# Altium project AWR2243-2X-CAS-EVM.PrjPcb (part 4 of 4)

## Sheet Enet_Conn.SchDoc
size 431 x 279 mm; Date: Not shown in title block; ApprovedBy: Not shown in title block; CheckedBy: Not shown in title block; Author: Not shown in title block; CompanyName: Not shown in title block; DrawnBy: B. Shaffer; Engineer: Not shown in title block; Organization: Not shown in title block; Address1: Not shown in title block; Address2: Not shown in title block; Address3: Not shown in title block; Address4: Not shown in title block; DocumentNumber: 12; Revision: Use project parameter SCH_Rev; SheetNumber: 12; SheetTotal: 17; PageSetup: Record=PageOptions¦CenterHorizontal=True¦CenterVertical=True¦PrintScale=1.00¦XCorrection=1.00¦YCorrection=1.00¦PrintKind=0¦BorderSize=5000000¦LeftOffset=0¦BottomOffset=0¦Orientation=2¦PaperLength=1000¦PaperWidth=1000¦Scale=100¦PaperSource=15¦PrintQuality=600¦MediaType=1¦DitherType=10¦PaperKind=Letter¦PrintScaleMode=1
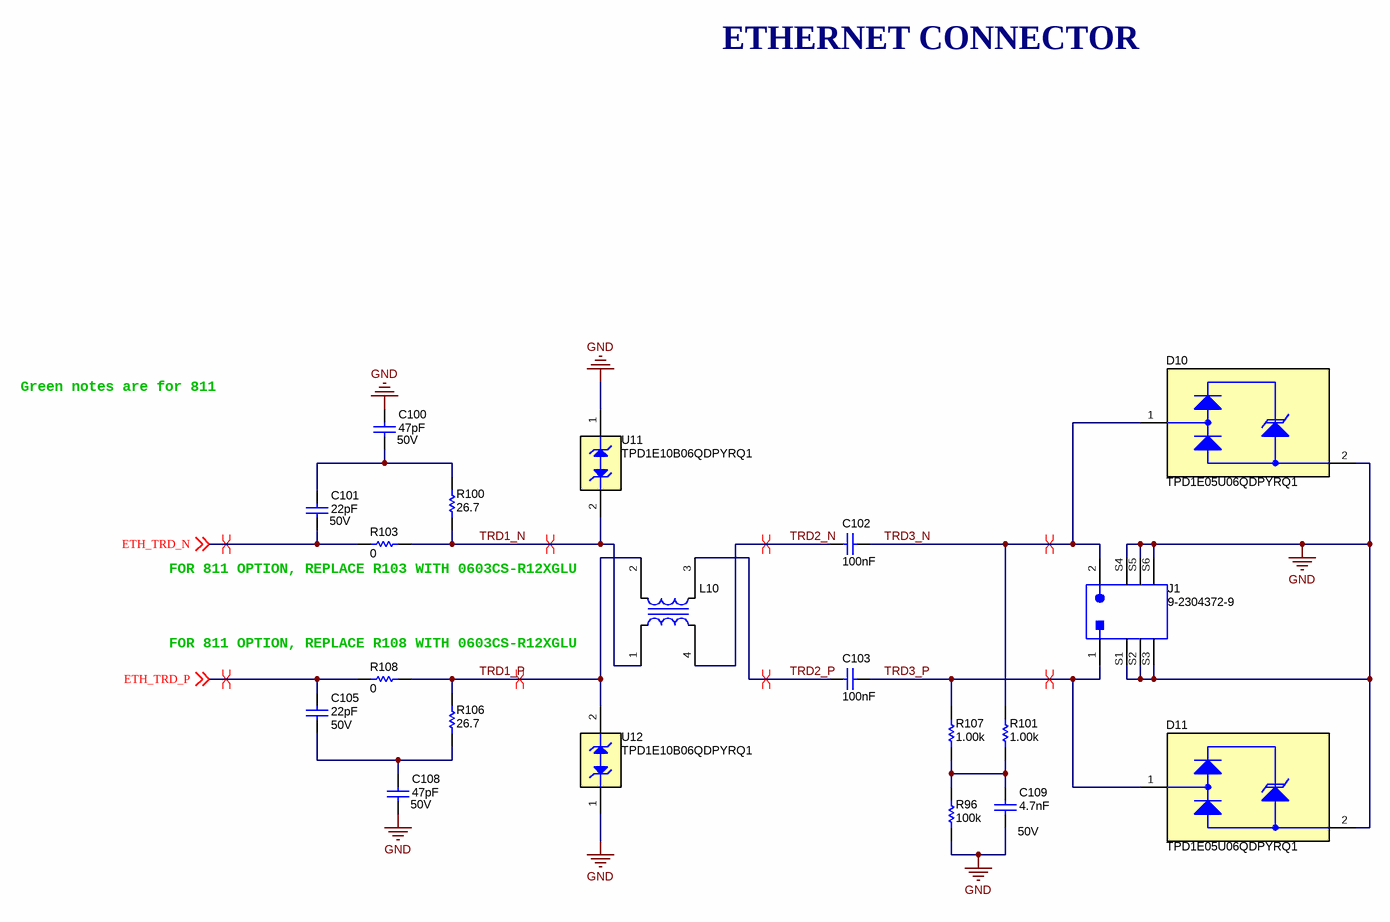
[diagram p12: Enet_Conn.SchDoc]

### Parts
C100  VDC_V: 50V  ValueDisplayed: 47pF  [0402]  (hidden comment: GRM1555C1H470FA01D)
C101  VDC_V: 50V  ValueDisplayed: 22pF  [0402]  (hidden comment: GRM1555C1H220FA01D)
C102  Cap_F: 100nF  [0805_HV]  (hidden comment: CGA4J2X7R2A104K125AA)
C103  Cap_F: 100nF  [0805_HV]  (hidden comment: CGA4J2X7R2A104K125AA)
C105  VDC_V: 50V  ValueDisplayed: 22pF  [0402]  (hidden comment: GRM1555C1H220FA01D)
C108  VDC_V: 50V  ValueDisplayed: 47pF  [0402]  (hidden comment: GRM1555C1H470FA01D)
C109  Cap_F: 4.7nF  VDC_V: 50V  [0805_HV]  (hidden comment: GCM216R71H472KA37D)
D10  TPD1E05U06QDPYRQ1  [DPY0002A]
D11  TPD1E05U06QDPYRQ1  [DPY0002A]
J1  9-2304372-9  [TE_9-2304372-9]
L10  ACT1210-101-2P-TL00  [TDK_ACT1210]  (value not drawn)
R96  ValueDisplayed: 100k  [0805_HV]  (hidden comment: CRCW0805100KJNEA)
R100  ValueDisplayed: 26.7  [0402]  (hidden comment: CRCW040226R7FKED)
R101  ValueDisplayed: 1.00k  [0402]  (hidden comment: CRCW04021K00FKED)
R103  ValueDisplayed: 0  [0603]  (hidden comment: RMCF0603ZT0R00)
R106  ValueDisplayed: 26.7  [0402]  (hidden comment: CRCW040226R7FKED)
R107  ValueDisplayed: 1.00k  [0402]  (hidden comment: CRCW04021K00FKED)
R108  ValueDisplayed: 0  [0603]  (hidden comment: RMCF0603ZT0R00)
U11  TPD1E10B06QDPYRQ1  [DPY0002A]
U12  TPD1E10B06QDPYRQ1  [DPY0002A]

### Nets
GND: C100.1 C108.2 C109.2 D10.2(GND) D11.2(GND) J1.S1(GND) J1.S2(GND) J1.S3(GND) J1.S4(GND) J1.S5(GND) J1.S6(GND) R96.1 U11.1(K) U12.1(K)
ETH_TRD_N: C101.2 R103.1 ; off-sheet ETH_TRD_N
ETH_TRD_P: C105.1 R108.1 ; off-sheet ETH_TRD_P
TRD1_N: L10.1 R100.1 R103.2 U11.2(A)
TRD1_P: L10.2 R106.2 R108.2 U12.2(A)
TRD2_N: C102.2 L10.4
TRD2_P: C103.2 L10.3
TRD3_N: C102.1 D10.1(I/O) J1.2 R101.2
TRD3_P: C103.1 D11.1(I/O) J1.1 R107.2
NetC100_2: C100.2 C101.1 R100.2
NetC105_2: C105.2 C108.1 R106.1
NetC109_1: C109.1 R96.2 R101.1 R107.1

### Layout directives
differential pair: ETH_TRD_N, ETH_TRD_P, TRD1_N, TRD1_P, TRD2_N, TRD2_P, TRD3_N, TRD3_P

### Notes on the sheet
- ETHERNET CONNECTOR
- Green notes are for 811
- (near R103) FOR 811 OPTION, REPLACE R103 WITH 0603CS-R12XGLU
- (near R108) FOR 811 OPTION, REPLACE R108 WITH 0603CS-R12XGLU

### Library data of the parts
C100 C108 = CMP-0006467-2: CAP, CERM, 47 pF, 50 V, +/- 1%, C0G/NP0, 0402; Manufacturer: MuRata; TaMin_C: -55°C; Polarized: N; SizeAreaWB_mm2: 3; Value1: Unknown; U/M: EA; Value: 47pF; TaMax_C: 125°C; SizeZ_mm: 0.6; SizeX_mm: 1; SizeY_mm: 0.5; CompType: Capacitor; AEC Category: Q200
C101 C105 = CMP-0006438-2: CAP, CERM, 22 pF, 50 V, +/- 1%, C0G/NP0, 0402; Manufacturer: MuRata; TaMin_C: -55°C; Polarized: N; SizeAreaWB_mm2: 3; Value1: Unknown; U/M: EA; Value: 22pF; TaMax_C: 125°C; SizeZ_mm: 0.6; SizeX_mm: 1; SizeY_mm: 0.5; CompType: Capacitor; AEC Category: Q200
C102 C103 = CMP-0007969-2: CAP, CERM, 0.1 uF, 100 V, +/- 10%, X7R, AEC-Q200 Grade 1, 0805; Manufacturer: TDK; TaMin_C: -55°C; ESR_ohm: 0.020726; Polarized: N; SizeAreaWB_mm2: 6.75; Value1: 0.020726 ohm; U/M: EA; Value: 0.1uF; TaMax_C: 125°C; SizeZ_mm: 1.45; SizeX_mm: 2; SizeY_mm: 1.25; Cap_Case: 0805; Value2: 100V; SizeArea_mm2: 2.5; AEC Qualified: Y; IRMS_A: 1.456A; AEC Grade: 1; AEC Category: Q200
C109 = CMP-0079078-1: CAP, CERM, 4700 pF, 50 V,+/- 10%, X7R, AEC-Q200 Grade 1, 0805; Manufacturer: MuRata; SizeAreaWB_mm2: 6.75; SizeArea_mm2: 2.5; AEC Qualified: Y; AEC Category: Q200; Value: 4700pF; TaMax_C: 125°C; SizeZ_mm: 1.45; AEC Grade: 1; Polarized: N; TaMin_C: -55°C; SizeY_mm: 1.25; U/M: EA; CompType: Capacitor; SizeX_mm: 2; Cap_Case: 0805
D10 D11 = CMP-0073591-4: Automotive 1-Channel Ultra-Low-Capacitance IEC ESD Protection Diode, DPY0002A (X1SON-2); Alternate Manufacturer: Texas Instruments; Alternate PartNumber: TPD1E05U06QDPYTQ1; SizeZ_mm: 0.45; SizeAreaWB_mm2: 3.2; SizeArea_mm2: 0.6; CompType: IC; AEC Category: Q200; AEC Qualified: Y; SizeX_mm: 1.0
J1 = CMP-0078655-1: 1 Port Header Assembly, TH; Manufacturer: TE Connectivity; Gender: Male; CompType: Connector; Shrouded: Y
L10 = CMP-0013193-2: Coupled inductor, 100 uH,  A, 1.5 ohm, SMD; Manufacturer: TDK; SizeAreaWB_mm2: 17.15; DCR_ohm: 1.5; Value: 100uH; SizeZ_mm: 2.5; SizeX_mm: 3.9; SizeArea_mm2: 9.75; Ind_H: 100µH
R96 = CMP-0020444-3: RES, 100 k, 5%, 0.125 W, AEC-Q200 Grade 0, 0805; Manufacturer: Vishay-Dale; Power_W: 125mW; TempCo: 200 ppm/C; Value: 100k; EIA_Code: E24; SizeX_mm: 2; SizeY_mm: 1.25; SizeZ_mm: 1.45; Value2: 0.125W; SizeArea_mm2: 2.5; AEC Qualified: Y; VDC_V: 150V; AEC Category: Q200; AEC Grade: 0
R100 = CMP-0026210-2: RES, 26.7, 1%, 0.063 W, AEC-Q200 Grade 0, 0402; Manufacturer: Vishay-Dale; Power_W: 63mW; TempCo: 100 ppm/C; Value_Code: 26R7; Value: 26.7; SizeX_mm: 1; SizeY_mm: 0.5; SizeZ_mm: 0.6; Value2: 0.063W; AEC Qualified: Y; VDC_V: 50V; AEC Grade: 0; AEC Category: Q200; EIA_Code: E96
R101 R107 = CMP-0026071-3: RES, 1.00 k, 1%, 0.063 W, AEC-Q200 Grade 0, 0402; Manufacturer: Vishay-Dale; Power_W: 63mW; TempCo: 100 ppm/C; Value_Code: 1k00; Value: 1.00k; EIA_Code: E96; Res_ohm: 1k; SizeX_mm: 1; SizeY_mm: 0.5; SizeZ_mm: 0.6; Value2: 0.063W; AEC Qualified: Y; VDC_V: 50V; AEC Category: Q200; AEC Grade: 0
R103 R108 = CMP-0023343-3: RES, 0, 1%, 0.1 W, AEC-Q200 Grade 0, 0603; Manufacturer: Stackpole Electronics Inc; Power_W: 100mW; TempCo: ppm/C; U/M: EA; Value: 0; SizeX_mm: 1.6; SizeY_mm: 0.8; SizeZ_mm: 1; Value2: 0.1W; SizeArea_mm2: 1.28; AEC Qualified: Y; AEC Category: Q200
R106 = CMP-0026210-2: RES, 26.7, 1%, 0.063 W, AEC-Q200 Grade 0, 0402; Manufacturer: Vishay-Dale; Power_W: 63mW; TempCo: 100 ppm/C; Value_Code: 26R7; Value: 26.7; SizeX_mm: 1; SizeY_mm: 0.5; SizeZ_mm: 0.6; Value2: 0.063W; CompType: Resistor; AEC Qualified: Y; VDC_V: 50V; AEC Grade: 0; AEC Category: Q200; EIA_Code: E96
U11 U12 = CMP-0073592-4: Automotive 1-Channel ESD in 0402 Package With 12pF Capacitance and 6V Breakdown, DPY0002A (X1SON-2); Manufacturer: Texas Instruments; Alternate PartNumber: TPD1E10B06DPYR; AEC Qualified: Y; AEC Category: Q200; CompType: IC; SizeAreaWB_mm2: 3.2; SizeZ_mm: 0.45; SizeY_mm: 0.6; SizeX_mm: 1.0

## Sheet Temp.schdoc: XDS110 Interface_1A
size 431 x 279 mm; Date: Not shown in title block; ApprovedBy: Not shown in title block; CheckedBy: Not shown in title block; Author: Not shown in title block; CompanyName: Not shown in title block; DrawnBy: B. Shaffer; Engineer: Not shown in title block; Organization: Not shown in title block; Address1: Not shown in title block; Address2: Not shown in title block; Address3: Not shown in title block; Address4: Not shown in title block; DocumentNumber: 13; Revision: Use project parameter SCH_Rev; SheetNumber: 13; SheetTotal: 17; PageSetup: Record=PageOptions¦CenterHorizontal=True¦CenterVertical=True¦PrintScale=1.00¦XCorrection=1.00¦YCorrection=1.00¦PrintKind=0¦BorderSize=5000000¦LeftOffset=0¦BottomOffset=0¦Orientation=2¦PaperLength=1000¦PaperWidth=1000¦Scale=100¦PaperSource=15¦PrintQuality=600¦MediaType=1¦DitherType=10¦PaperKind=Letter¦PrintScaleMode=1
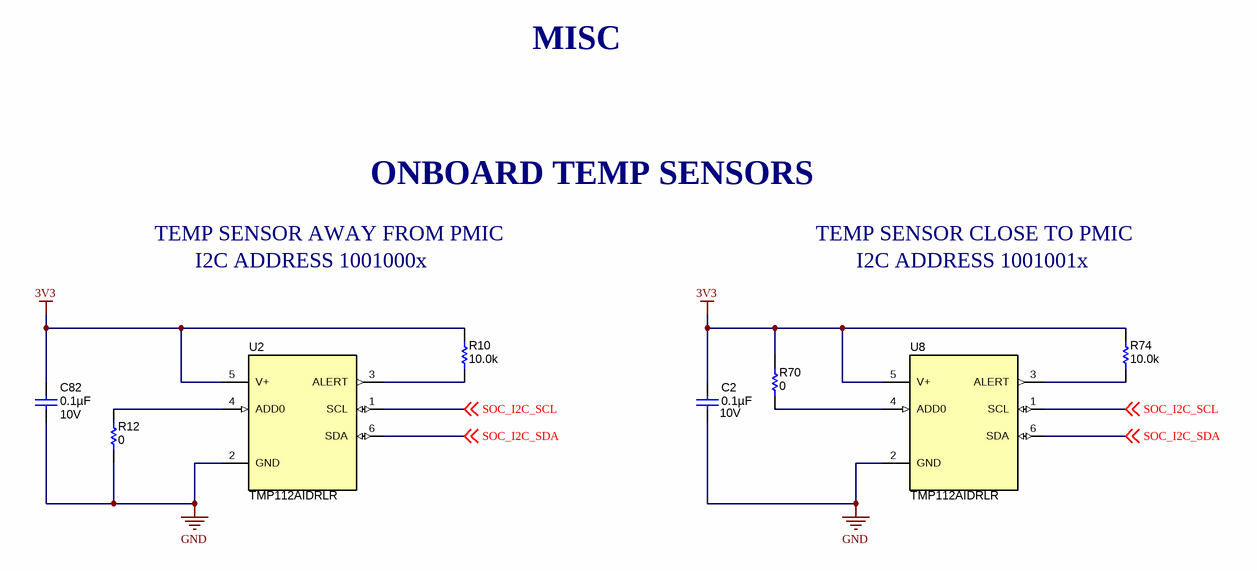
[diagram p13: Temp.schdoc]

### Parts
C2  VDC_V: 10V  ValueDisplayed: 0.1µF  [0402L]  (hidden comment: CGA4J3X7R1H225K125AB)
C82  VDC_V: 10V  ValueDisplayed: 0.1µF  [0402L]  (hidden comment: C0402C104K8RACTU)
R10  ValueDisplayed: 10.0k  [0402L]  (hidden comment: CRCW040210K0FKED)
R12  ValueDisplayed: 0  [0402]  (hidden comment: CRCW04020000Z0ED)
R70  ValueDisplayed: 0  [0402]  (hidden comment: CRCW04020000Z0ED)
R74  ValueDisplayed: 10.0k  [0402L]  (hidden comment: ERJ-2GE0R00X)
U2  TMP112AIDRLR  [DRL0006A]
U8  TMP112AIDRLR  [DRL0006A]

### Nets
3V3: C2.2 C82.1 R10.1 R70.1 R74.1 U2.5(V+) U8.5(V+)
GND: C2.1 C82.2 R12.2 U2.2(GND) U8.2(GND)
SOC_I2C_SCL: U2.1(SCL) U8.1(SCL) ; off-sheet SOC_I2C_SCL
SOC_I2C_SDA: U2.6(SDA) U8.6(SDA) ; off-sheet SOC_I2C_SDA
NetR10_2: R10.2 U2.3(ALERT)
NetR12_1: R12.1 U2.4(ADD0)
NetR70_2: R70.2 U8.4(ADD0)
NetR74_2: R74.2 U8.3(ALERT)

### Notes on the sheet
- MISC
- ONBOARD TEMP SENSORS
- TEMP SENSOR AWAY FROM PMIC
- I2C ADDRESS 1001000x
- TEMP SENSOR CLOSE TO PMIC
- I2C ADDRESS 1001001x

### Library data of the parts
C2 = CMP-0078241-1: CAP, CERM, 0.1 µF, 10 V,+/- 10%, X7R, 0402; Manufacturer: Kemet; PartNumber: C0402C104K8RACTU; TaMin_C: -55°C; Polarized: N; SizeAreaWB_mm2: 3; U/M: EA; Value: 0.1uF; TaMax_C: 125°C; SizeZ_mm: 0.6; SizeX_mm: 1; SizeY_mm: 0.5; Cap_Case: 0402; CompType: Capacitor; Cap_F: 100nF; AEC Category: Q200
C82 = CMP-0078241-1: CAP, CERM, 0.1 µF, 10 V,+/- 10%, X7R, 0402; Manufacturer: Kemet; TaMin_C: -55°C; Polarized: N; SizeAreaWB_mm2: 3; U/M: EA; Value: 0.1uF; TaMax_C: 125°C; SizeZ_mm: 0.6; SizeX_mm: 1; SizeY_mm: 0.5; Cap_Case: 0402; CompType: Capacitor; Cap_F: 100nF; AEC Category: Q200
R10 = CMP-0025958-3: RES, 10.0 k, 1%, 0.063 W, AEC-Q200 Grade 0, 0402; Manufacturer: Vishay-Dale; Power_W: 63mW; TempCo: 100 ppm/C; Value_Code: 10k0; Value: 10.0k; EIA_Code: E96; Res_ohm: 10k; SizeX_mm: 1; SizeY_mm: 0.5; SizeZ_mm: 0.6; Value2: 0.063W; AEC Qualified: Y; VDC_V: 50V; AEC Category: Q200; AEC Grade: 0
R12 R70 = CMP-0026822-3: RES, 0, 5%, 0.063 W, AEC-Q200 Grade 0, 0402; Manufacturer: Vishay-Dale; Power_W: 63mW; TempCo: 200 ppm/C; Value_Code: 0000; Value: 0; EIA_Code: E24; SizeX_mm: 1; SizeY_mm: 0.5; SizeZ_mm: 0.6; Value2: 0.063W; AEC Qualified: Y; VDC_V: 50V; AEC Category: Q200
R74 = CMP-0025958-3: RES, 10.0 k, 1%, 0.063 W, AEC-Q200 Grade 0, 0402; Manufacturer: Vishay-Dale; PartNumber: CRCW040210K0FKED; Power_W: 63mW; TempCo: 100 ppm/C; Value_Code: 10k0; Value: 10.0k; EIA_Code: E96; Res_ohm: 10k; SizeX_mm: 1; SizeY_mm: 0.5; SizeZ_mm: 0.6; Value2: 0.063W; CompType: Resistor; AEC Qualified: Y; VDC_V: 50V; AEC Category: Q200; AEC Grade: 0
U2 U8 = CMP-0067397-2: 1.4V-Capable +/-0.5degC Temperature Sensor with Alert Function and I2C/SMBus interface in SOT-563, DRL0006A (SOT-OTHER-6); Alternate PartNumber: TMP112AIDRLT; Alternate Manufacturer: Texas Instruments; Green_Lifecycle: Active; SizeAreaWB_mm2: 6.76; Green_REACh: Passed; U/M: EA; SizeZ_mm: 0.6; SizeX_mm: 1.6; SizeArea_mm2: 2.56; CompType: IC

## Sheet Connectors.schdoc
size 431 x 279 mm; Date: Not shown in title block; ApprovedBy: Not shown in title block; CheckedBy: Not shown in title block; Author: Not shown in title block; CompanyName: Not shown in title block; DrawnBy: B. Shaffer; Engineer: Not shown in title block; Organization: Not shown in title block; Address1: Not shown in title block; Address2: Not shown in title block; Address3: Not shown in title block; Address4: Not shown in title block; DocumentNumber: 14; Revision: Use project parameter SCH_Rev; SheetNumber: 14; SheetTotal: 17; PageSetup: Record=PageOptions¦CenterHorizontal=True¦CenterVertical=True¦PrintScale=1.00¦XCorrection=1.00¦YCorrection=1.00¦PrintKind=0¦BorderSize=5000000¦LeftOffset=0¦BottomOffset=0¦Orientation=2¦PaperLength=1000¦PaperWidth=1000¦Scale=100¦PaperSource=15¦PrintQuality=600¦MediaType=1¦DitherType=10¦PaperKind=Letter¦PrintScaleMode=1
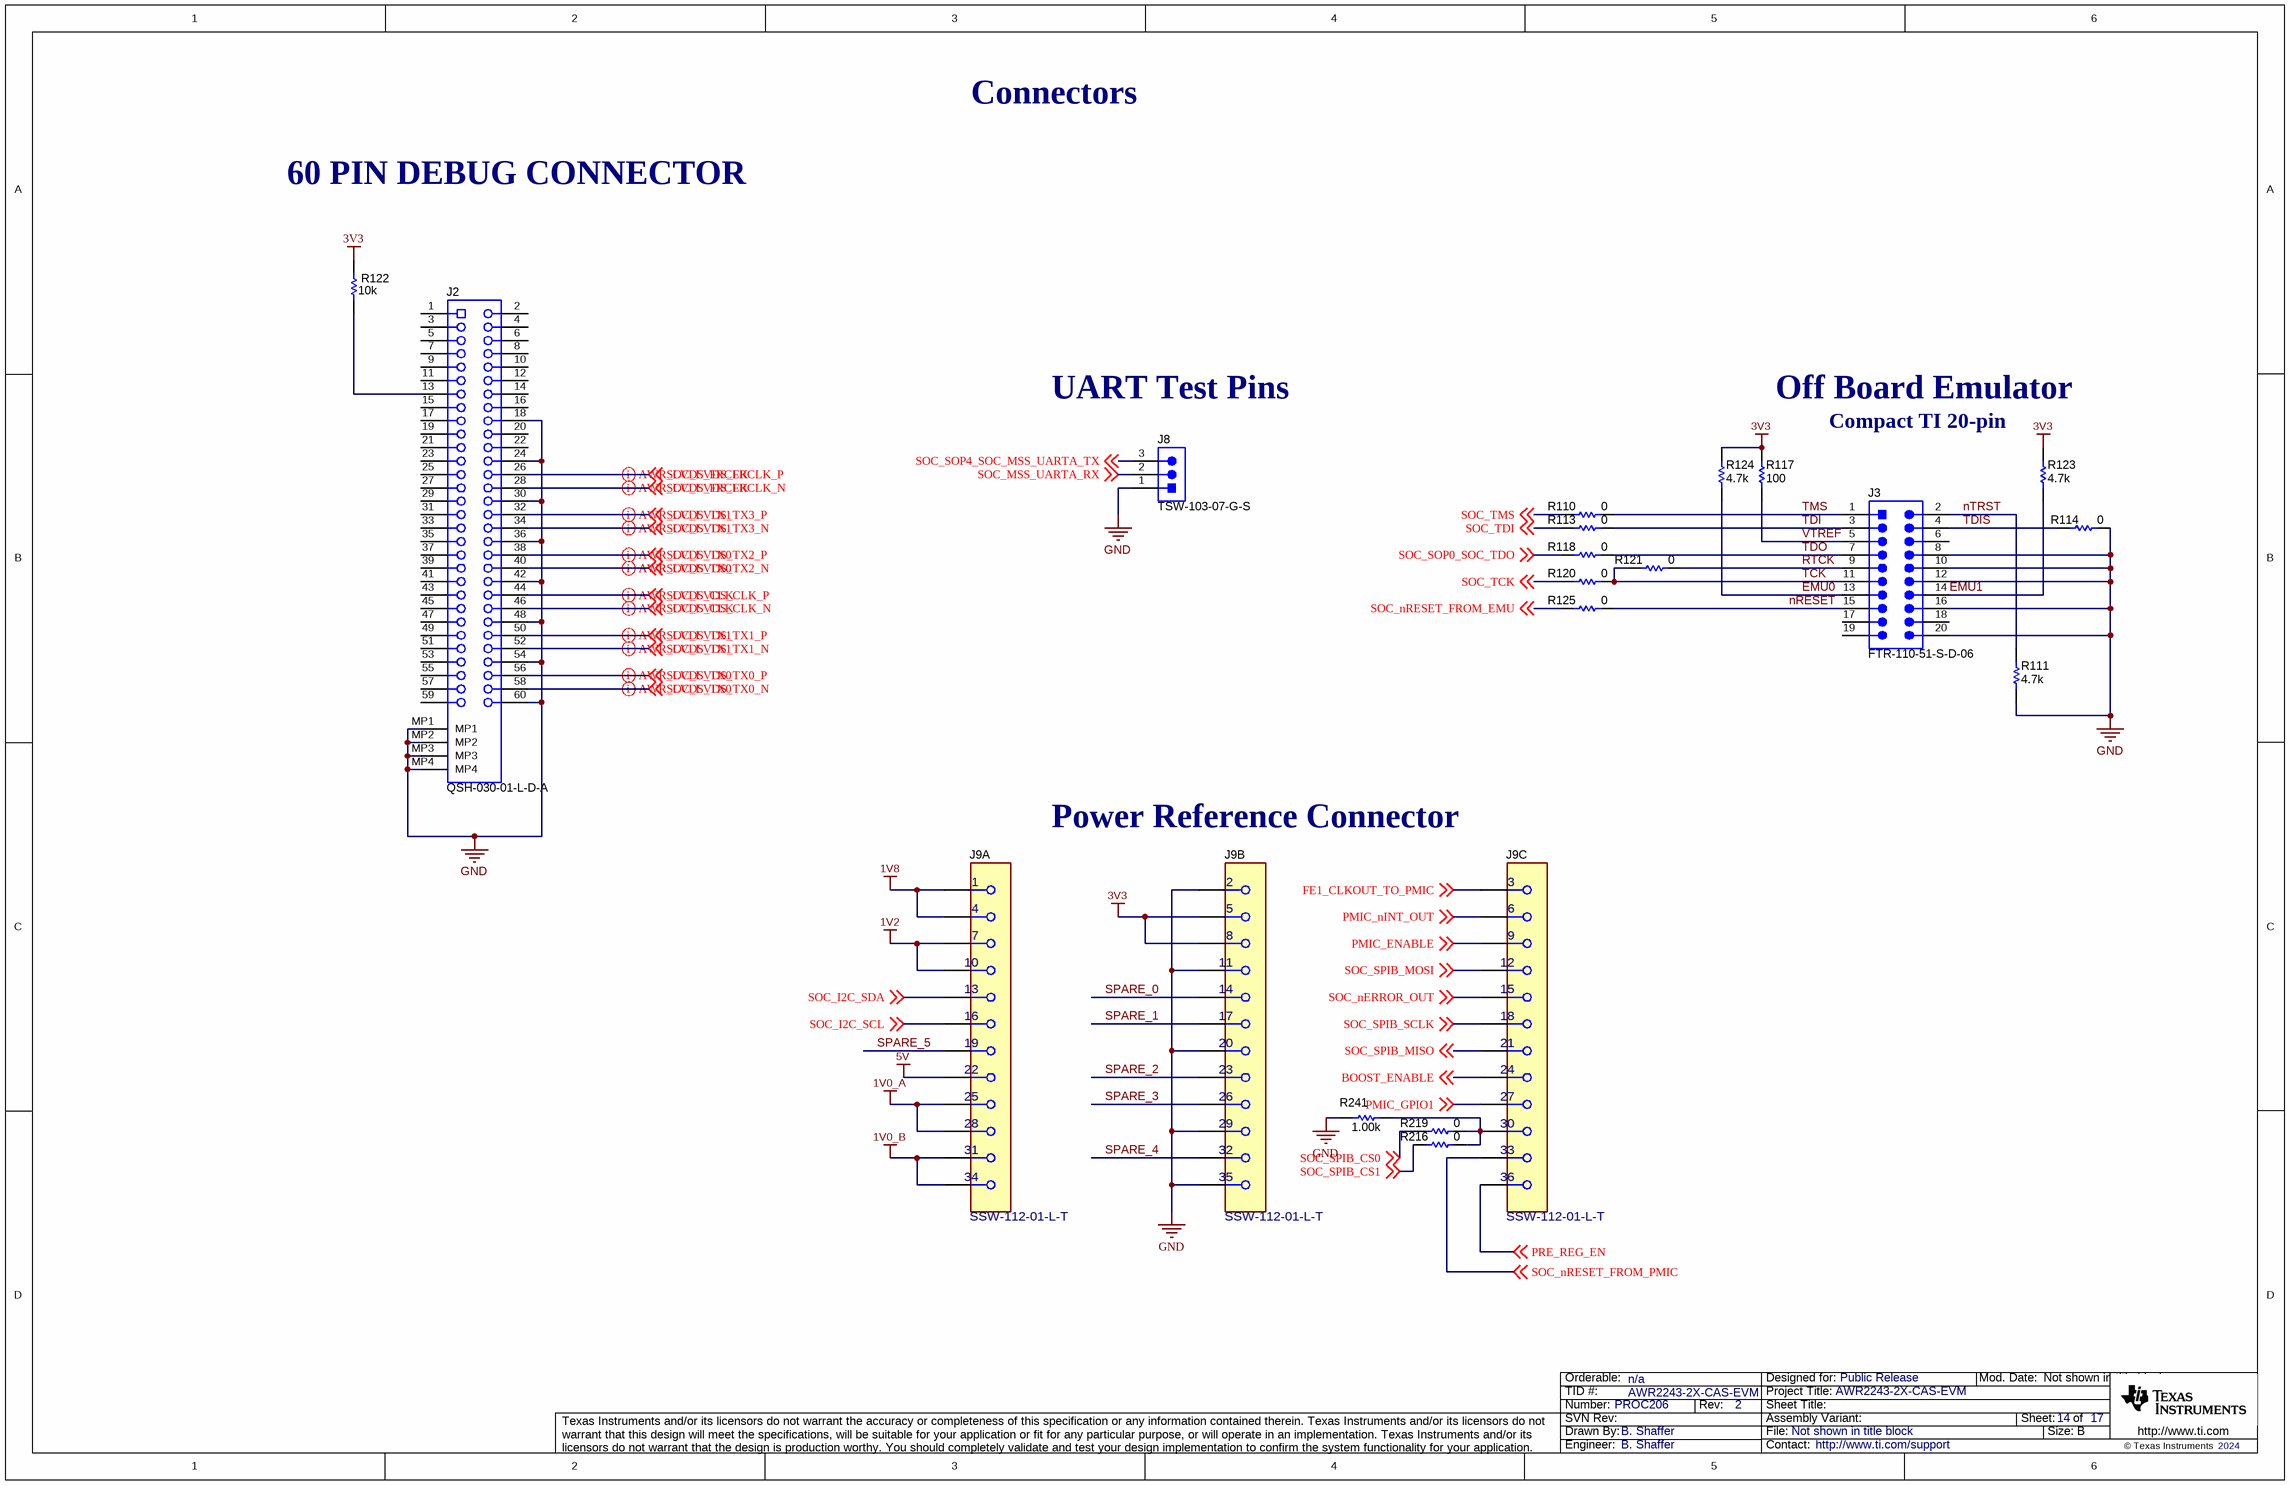
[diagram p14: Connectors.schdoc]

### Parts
J2  QSH-030-01-L-D-A  [Samtec_QSH-030-01-X-D-A]
J3  FTR-110-51-S-D-06  [Samtec_FTR-110-51-x-D-06]
J8  TSW-103-07-G-S  [TSW-103-07-X-S]
J9  SSW-112-01-L-T  [FP-SSW-112-01-L-T_HDR36-MFG]  (parts A,B,C of 3)
R110  ValueDisplayed: 0  [0402]  (hidden comment: CRCW04020000Z0ED)
R111  ValueDisplayed: 4.7k  [0402]  (hidden comment: CRCW04024K70JNED)
R113  ValueDisplayed: 0  [0402]  (hidden comment: CRCW04020000Z0ED)
R114  ValueDisplayed: 0  [0402]  (hidden comment: CRCW04020000Z0ED)
R117  ValueDisplayed: 100  [0402]  (hidden comment: CRCW0402100RJNED)
R118  ValueDisplayed: 0  [0402]  (hidden comment: CRCW04020000Z0ED)
R120  ValueDisplayed: 0  [0402]  (hidden comment: CRCW04020000Z0ED)
R121  ValueDisplayed: 0  [0402]  (hidden comment: CRCW04020000Z0ED)
R122  ValueDisplayed: 10k  [0402]  (hidden comment: CRCW040210K0JNED)
R123  ValueDisplayed: 4.7k  [0402]  (hidden comment: CRCW04024K70JNED)
R124  ValueDisplayed: 4.7k  [0402]  (hidden comment: CRCW04024K70JNED)
R125  ValueDisplayed: 0  [0402]  (hidden comment: CRCW04020000Z0ED)
R216  ValueDisplayed: 0  [0402]  (hidden comment: CRCW04020000Z0ED)
R219  ValueDisplayed: 0  [0402]  (hidden comment: CRCW04020000Z0ED)
R241  ValueDisplayed: 1.00k  [0402]  (hidden comment: CRCW04021K00FKED)

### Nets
1V0_A: J9.25 J9.28
1V0_B: J9.31 J9.34
1V2: J9.7 J9.10
1V8: J9.1 J9.4
3V3: J9.5 J9.8 R117.2 R122.2 R123.2 R124.2
5V: J9.22
GND: J2.18 J2.24 J2.30 J2.36 J2.42 J2.48 J2.54 J2.60 J2.MP1 J2.MP2 J2.MP3 J2.MP4 J3.8 J3.10 J3.12 J3.16 J3.20 J8.1 J9.2 J9.11 J9.20 J9.29 J9.35 R111.1 R114.1 R241.2
BOOST_ENABLE: J9.24 ; off-sheet BOOST_ENABLE
EMU0: J3.13 R124.1
EMU1: J3.14 R123.1
FE1_CLKOUT_TO_PMIC: J9.3 ; off-sheet FE1_CLKOUT_TO_PMIC
nRESET: J3.15 R125.1
nTRST: J3.2 R111.2
PMIC_ENABLE: J9.9 ; off-sheet PMIC_ENABLE
PMIC_GPIO1: J9.27 ; off-sheet PMIC_GPIO1
PMIC_nINT_OUT: J9.6 ; off-sheet PMIC_nINT_OUT
PRE_REG_EN: J9.36 ; off-sheet PRE_REG_EN
RTCK: J3.9 R121.1
SOC_I2C_SCL: J9.16 ; off-sheet SOC_I2C_SCL
SOC_I2C_SDA: J9.13 ; off-sheet SOC_I2C_SDA
SOC_LVDS_CLK_N: J2.46 ; off-sheet SOC_LVDS_CLK_N
SOC_LVDS_CLK_P: J2.44 ; off-sheet SOC_LVDS_CLK_P
SOC_LVDS_FRCLK_N: J2.28 ; off-sheet SOC_LVDS_FRCLK_N
SOC_LVDS_FRCLK_P: J2.26 ; off-sheet SOC_LVDS_FRCLK_P
SOC_LVDS_TX0_N: J2.58 ; off-sheet SOC_LVDS_TX0_N
SOC_LVDS_TX0_P: J2.56 ; off-sheet SOC_LVDS_TX0_P
SOC_LVDS_TX1_N: J2.52 ; off-sheet SOC_LVDS_TX1_N
SOC_LVDS_TX1_P: J2.50 ; off-sheet SOC_LVDS_TX1_P
SOC_LVDS_TX2_N: J2.40 ; off-sheet SOC_LVDS_TX2_N
SOC_LVDS_TX2_P: J2.38 ; off-sheet SOC_LVDS_TX2_P
SOC_LVDS_TX3_N: J2.34 ; off-sheet SOC_LVDS_TX3_N
SOC_LVDS_TX3_P: J2.32 ; off-sheet SOC_LVDS_TX3_P
SOC_MSS_UARTA_RX: J8.2 ; off-sheet SOC_MSS_UARTA_RX
SOC_nERROR_OUT: J9.15 ; off-sheet SOC_nERROR_OUT
SOC_nRESET_FROM_EMU: R125.2 ; off-sheet SOC_nRESET_FROM_EMU
SOC_nRESET_FROM_PMIC: J9.33 ; off-sheet SOC_nRESET_FROM_PMIC
SOC_SOP0_SOC_TDO: R118.2 ; off-sheet SOC_SOP0_SOC_TDO
SOC_SOP4_SOC_MSS_UARTA_TX: J8.3 ; off-sheet SOC_SOP4_SOC_MSS_UARTA_TX
SOC_SPIB_CS0: R219.2 ; off-sheet SOC_SPIB_CS0
SOC_SPIB_CS1: R216.2 ; off-sheet SOC_SPIB_CS1
SOC_SPIB_MISO: J9.21 ; off-sheet SOC_SPIB_MISO
SOC_SPIB_MOSI: J9.12 ; off-sheet SOC_SPIB_MOSI
SOC_SPIB_SCLK: J9.18 ; off-sheet SOC_SPIB_SCLK
SOC_TCK: R120.2 ; off-sheet SOC_TCK
SOC_TDI: R113.2 ; off-sheet SOC_TDI
SOC_TMS: R110.2 ; off-sheet SOC_TMS
SPARE_0: J9.14
SPARE_1: J9.17
SPARE_2: J9.23
SPARE_3: J9.26
SPARE_4: J9.32
SPARE_5: J9.19
TCK: J3.11 R120.1 R121.2
TDI: J3.3 R113.1
TDIS: J3.4 R114.2
TDO: J3.7 R118.1
TMS: J3.1 R110.1
VTREF: J3.5 R117.1
NetJ2_13: J2.13 R122.1
NetJ9_30: J9.30 R216.1 R219.1 R241.1

Not connected (* = marked no-connect by the designer): J2 1 2 3 4 5 6 7 8 9 10 11 12 14 15 16 17 19 20 21 22 23 25 27 29 31 33 35 37 39 41 43 45 47 49 51 53 55 57 59; J3 6 17 18 19

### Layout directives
differential pair: SOC_LVDS_CLK_N, SOC_LVDS_CLK_P, SOC_LVDS_FRCLK_N, SOC_LVDS_FRCLK_P, SOC_LVDS_TX0_N, SOC_LVDS_TX0_P, SOC_LVDS_TX1_N, SOC_LVDS_TX1_P, SOC_LVDS_TX2_N, SOC_LVDS_TX2_P, SOC_LVDS_TX3_N, SOC_LVDS_TX3_P

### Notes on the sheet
- Connectors
- 60 PIN DEBUG CONNECTOR
- UART Test Pins
- Off Board Emulator
- (near R123) Compact TI 20-pin
- Power Reference Connector

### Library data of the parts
J2 = CMP-0075524-1: Receptacle, 0.5 mm, 30x2, Gold, TH; Manufacturer: Samtec; Pitch_mm: 0.5; Gender: Female; Green_REACh: Passed; CT: False; Shrouded: N; RowSpacing_mm: 5.73; Green_Lifecycle: Active; Row_Count: 2
J3 = CMP-0075640-2: Header, 1.27mm, 10x2, Tin, SMT; Manufacturer: Samtec; Pitch_mm: 1.27; Gender: Male; Cert_UL: Y; Green_REACh: Passed; Current_A: 3.1A; Shrouded: N; RowSpacing_mm: 2.54; Green_Lifecycle: Active; Row_Count: 2
J8 = CMP-0075407-1: Header, 100mil, 3x1, Gold, TH; Manufacturer: Samtec; Pitch_mm: 2.54; Cert_VDE: N; Gender: Male; Cert_CSA: Y; Voltage_V: 550V; Green_REACh: Passed; Current_A: 6.3A; CT: False; Green_Lifecycle: Active; Row_Count: 1; CNHeader: True
J9 = CMP-0087935-1: Board-To-Board Connector, SSW Series, 32 Contacts, Receptacle, 2.54 mm, Through Hole, 3 Rows; Manufacturer: Samtec; Current_A: 4.7A; Row_Count: 3; Voltage_V: 655V; ContactFinish: Gold,Nickel
R110 R113 R118 R120 R121 R125 R216 R219 = CMP-0026822-3: as R12 on sheet Temp
R111 R123 R124 = CMP-0026938-5: RES, 4.7 k, 5%, 0.063 W, AEC-Q200 Grade 0, 0402; Manufacturer: Vishay-Dale; Power_W: 63mW; TempCo: 200 ppm/C; Value_Code: 4k70; Value: 4.7k; EIA_Code: E24; SizeX_mm: 1; SizeY_mm: 0.5; SizeZ_mm: 0.6; Value2: 0.063W; AEC Qualified: Y; VDC_V: 50V; AEC Category: Q200; AEC Grade: 0
R114 = CMP-0026822-3: RES, 0, 5%, 0.063 W, AEC-Q200 Grade 0, 0402; Manufacturer: Vishay-Dale; Power_W: 63mW; TempCo: 200 ppm/C; Value_Code: 0000; Value: 0; EIA_Code: E24; SizeX_mm: 1; SizeY_mm: 0.5; SizeZ_mm: 0.6; Value2: 0.063W; CompType: Resistor; AEC Qualified: Y; VDC_V: 50V; AEC Category: Q200
R117 = CMP-0026824-3: RES, 100, 5%, 0.063 W, AEC-Q200 Grade 0, 0402; Manufacturer: Vishay-Dale; Power_W: 63mW; TempCo: 200 ppm/C; Value_Code: 100R; Value: 100; EIA_Code: E24; SizeX_mm: 1; SizeY_mm: 0.5; SizeZ_mm: 0.6; Value2: 0.063W; AEC Qualified: Y; VDC_V: 50V; AEC Category: Q200; AEC Grade: 0
R122 = CRCW040210K0JNED: RES, 10 k, 5%, 0.063 W, 0402; Manufacturer: Vishay-Dale; CompType: Resistor; Value: 10k; Res_ohm: 10000; Value_Code: 10k0; Tolerance_%: 5; Power_W: 0.063; Value2: 0.063W; VDC_V: 50; TempCo: 200 ppm/C; SizeArea_mm2: 0.5; SizeX_mm: 1; SizeZ_mm: 0.6; EIA_Code: E24; U/M: EA; AEC Category: Q200
R241 = CMP-0026071-3: as R101 on sheet Enet_Conn

## Sheet Clock_Buff.SchDoc: PMIC
size 431 x 279 mm; Date: Not shown in title block; ApprovedBy: Not shown in title block; CheckedBy: Not shown in title block; Author: Not shown in title block; CompanyName: Not shown in title block; DrawnBy: B. Shaffer; Engineer: Not shown in title block; Organization: Not shown in title block; Address1: Not shown in title block; Address2: Not shown in title block; Address3: Not shown in title block; Address4: Not shown in title block; DocumentNumber: 15; Revision: Use project parameter SCH_Rev; SheetNumber: 15; SheetTotal: 17; PageSetup: Record=PageOptions¦CenterHorizontal=True¦CenterVertical=True¦PrintScale=1.00¦XCorrection=1.00¦YCorrection=1.00¦PrintKind=0¦BorderSize=5000000¦LeftOffset=0¦BottomOffset=0¦Orientation=2¦PaperLength=1000¦PaperWidth=1000¦Scale=100¦PaperSource=15¦PrintQuality=600¦MediaType=1¦DitherType=10¦PaperKind=Letter¦PrintScaleMode=1
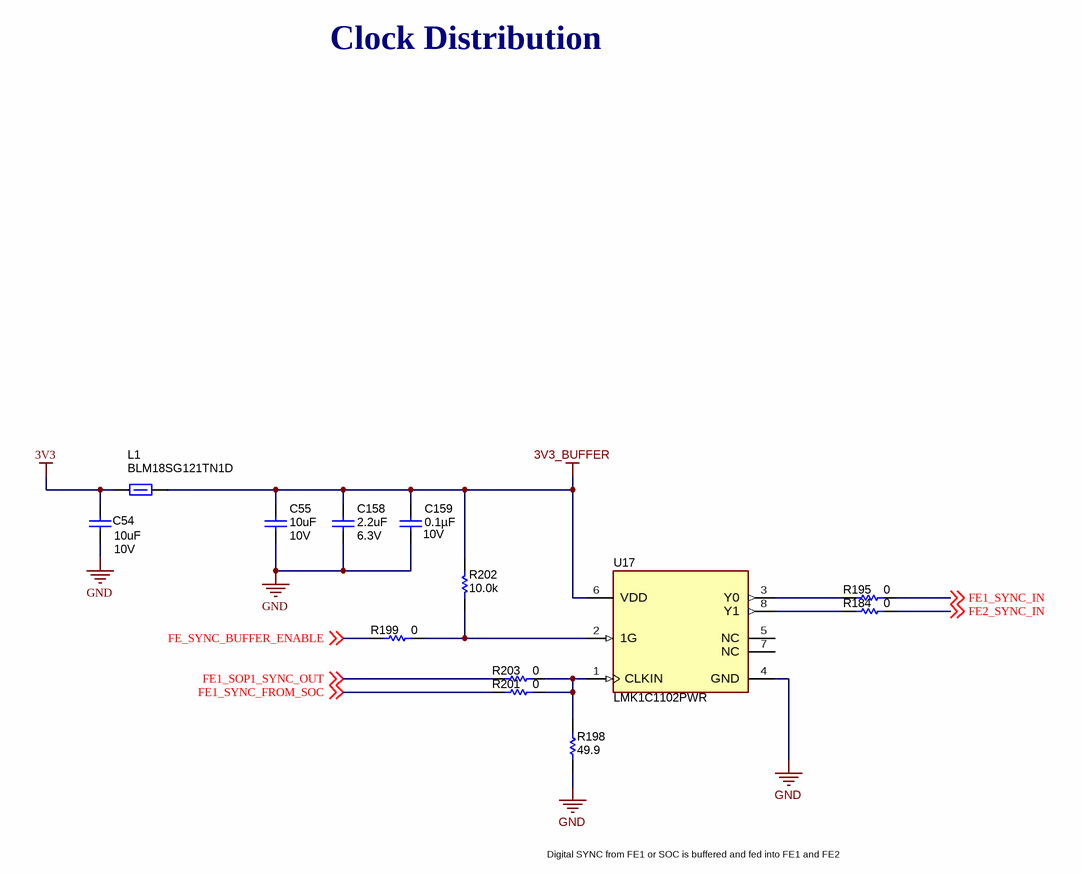
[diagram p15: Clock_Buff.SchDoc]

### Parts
C54  VDC_V: 10V  ValueDisplayed: 10uF  [0805_HV]  (hidden comment: GCM21BR71A106KE22L)
C55  VDC_V: 10V  ValueDisplayed: 10uF  [0805_HV]  (hidden comment: C2012X7R1C225K125AB)
C158  VDC_V: 6.3V  ValueDisplayed: 2.2uF  [0402]  (hidden comment: CGA2B3X7R1H104K050BB)
C159  VDC_V: 10V  ValueDisplayed: 0.1µF  [0402L]  (hidden comment: C0402C104K8RACTU)
L1  BLM18SG121TN1D  [0603]
R184  ValueDisplayed: 0  [0402]  (hidden comment: CRCW04020000Z0ED)
R195  ValueDisplayed: 0  [0402]  (hidden comment: CRCW04020000Z0ED)
R198  ValueDisplayed: 49.9  [0402]  (hidden comment: CRCW040249R9FKED)
R199  ValueDisplayed: 0  [0402]  (hidden comment: CRCW04020000Z0ED)
R201  ValueDisplayed: 0  [0402]  (hidden comment: CRCW04020000Z0ED)
R202  ValueDisplayed: 10.0k  [0402]  (hidden comment: CRCW040210K0FKED)
R203  ValueDisplayed: 0  [0402]  (hidden comment: CRCW04020000Z0ED)
U17  LMK1C1102PWR  [PW0008A-MFG]

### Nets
3V3: C54.1 L1.1
3V3_BUFFER: C55.2 C158.2 C159.1 L1.2 R202.2 U17.6(VDD)
GND: C54.2 C55.1 C158.1 C159.2 R198.1 U17.4(GND)
FE1_SOP1_SYNC_OUT: R203.2 ; off-sheet FE1_SOP1_SYNC_OUT
FE1_SYNC_FROM_SOC: R201.2 ; off-sheet FE1_SYNC_FROM_SOC
FE1_SYNC_IN: R195.1 ; off-sheet FE1_SYNC_IN
FE2_SYNC_IN: R184.1 ; off-sheet FE2_SYNC_IN
FE_SYNC_BUFFER_ENABLE: R199.2 ; off-sheet FE_SYNC_BUFFER_ENABLE
NetR184_2: R184.2 U17.8(Y1)
NetR195_2: R195.2 U17.3(Y0)
NetR198_2: R198.2 R201.1 R203.1 U17.1(CLKIN)
NetR199_1: R199.1 R202.1 U17.2(1G)

Not connected (* = marked no-connect by the designer): U17 5(NC) 7(NC)

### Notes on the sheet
- Clock Distribution
- Digital SYNC from FE1 or SOC is buffered and fed into FE1 and FE2

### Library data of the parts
C54 = CMP-0008017-2: CAP, CERM, 10 uF, 10 V, +/- 10%, X7R, 0805; Manufacturer: MuRata; TaMin_C: -55°C; Polarized: N; SizeAreaWB_mm2: 6.75; Value1: Unknown; U/M: EA; Value: 10uF; TaMax_C: 125°C; SizeZ_mm: 1.45; SizeX_mm: 2; SizeY_mm: 1.25; Cap_Case: 0805; SizeArea_mm2: 2.5; CompType: Capacitor; Cap_F: 10µF; AEC Category: Q200
C55 = CMP-0008017-2: CAP, CERM, 10 uF, 10 V, +/- 10%, X7R, 0805; Manufacturer: MuRata; PartNumber: GCM21BR71A106KE22L; TaMin_C: -55°C; Polarized: N; SizeAreaWB_mm2: 6.75; Value1: Unknown; U/M: EA; Value: 10uF; TaMax_C: 125°C; SizeZ_mm: 1.45; SizeX_mm: 2; SizeY_mm: 1.25; Cap_Case: 0805; SizeArea_mm2: 2.5; CompType: Capacitor; Cap_F: 10µF; AEC Category: Q200
C158 = CMP-0007134-5: CAP, CERM, 2.2 uF, 6.3 V, +/- 10%, X7R, AEC-Q200 Grade 1, 0603; Manufacturer: MuRata; PartNumber: GCM188R70J225KE22D; TaMin_C: -55°C; Polarized: N; SizeAreaWB_mm2: 4.68; Value1: Unknown; U/M: EA; Value: 2.2uF; TaMax_C: 125°C; SizeZ_mm: 1; SizeX_mm: 1.6; SizeY_mm: 0.8; Cap_Case: 0603; SizeArea_mm2: 1.28; AEC Qualified: Y; Cap_F: 2.2µF; AEC Category: Q200
C159 = CMP-0078241-1: as C82 on sheet Temp
L1 = CMP-0003352-2: Ferrite Bead, 120 ohm @ 100 MHz, 3 A, 0603; Manufacturer: MuRata; ZTyp@100MHz_Ohm: 120; SizeAreaWB_mm2: 4.68; DCR_ohm: 0.025; Value1: 0.025 ohm; Value: 120 ohm; Imax_A: 3A; SizeZ_mm: 1; SizeX_mm: 1.6; SizeY_mm: 0.8; SizeArea_mm2: 1.28
R184 R195 R199 R201 R203 = CMP-0026822-3: as R12 on sheet Temp
R198 = CMP-0026404-2: RES, 49.9, 1%, 0.063 W, AEC-Q200 Grade 0, 0402; Manufacturer: Vishay-Dale; Power_W: 63mW; TempCo: 100 ppm/C; Value_Code: 49R9; Value: 49.9; EIA_Code: E96; SizeX_mm: 1; SizeY_mm: 0.5; SizeZ_mm: 0.6; Value2: 0.063W; AEC Qualified: Y; VDC_V: 50V; AEC Category: Q200; AEC Grade: 0
R202 = CMP-0025958-3: RES, 10.0 k, 1%, 0.063 W, AEC-Q200 Grade 0, 0402; Manufacturer: Vishay-Dale; Power_W: 63mW; TempCo: 100 ppm/C; Value_Code: 10k0; Value: 10.0k; EIA_Code: E96; Res_ohm: 10k; SizeX_mm: 1; SizeY_mm: 0.5; SizeZ_mm: 0.6; Value2: 0.063W; CompType: Resistor; AEC Qualified: Y; VDC_V: 50V; AEC Category: Q200; AEC Grade: 0; INSTALLATION: DNP
U17 = CMP-0091149-1: Manufacturer: Texas Instruments; Standoff Height: 0.05mm; SizeZ_mm: 1.2mm; Propagation Delay: 1.5ns; AEC Qualified: No; Number Of Outputs: 2; Nominal Supply Current: 25-33000uA; TaMin_C: -40°C; Min Supply Voltage: 1.71V; Max Supply Voltage: 3.465V; Number Of Elements: 1; TJmax_C: +150°C; TaMax_C: +125°C

## Sheet XDS110.schdoc
size 431 x 279 mm; Date: Not shown in title block; ApprovedBy: Not shown in title block; CheckedBy: Not shown in title block; Author: Not shown in title block; CompanyName: Not shown in title block; DrawnBy: B. Shaffer; Engineer: Not shown in title block; Organization: Not shown in title block; Address1: Not shown in title block; Address2: Not shown in title block; Address3: Not shown in title block; Address4: Not shown in title block; DocumentNumber: 16; Revision: Use project parameter SCH_Rev; SheetNumber: 16; SheetTotal: 17; PageSetup: Record=PageOptions¦CenterHorizontal=True¦CenterVertical=True¦PrintScale=1.00¦XCorrection=1.00¦YCorrection=1.00¦PrintKind=0¦BorderSize=5000000¦LeftOffset=0¦BottomOffset=0¦Orientation=2¦PaperLength=1000¦PaperWidth=1000¦Scale=100¦PaperSource=15¦PrintQuality=600¦MediaType=1¦DitherType=10¦PaperKind=Letter¦PrintScaleMode=1
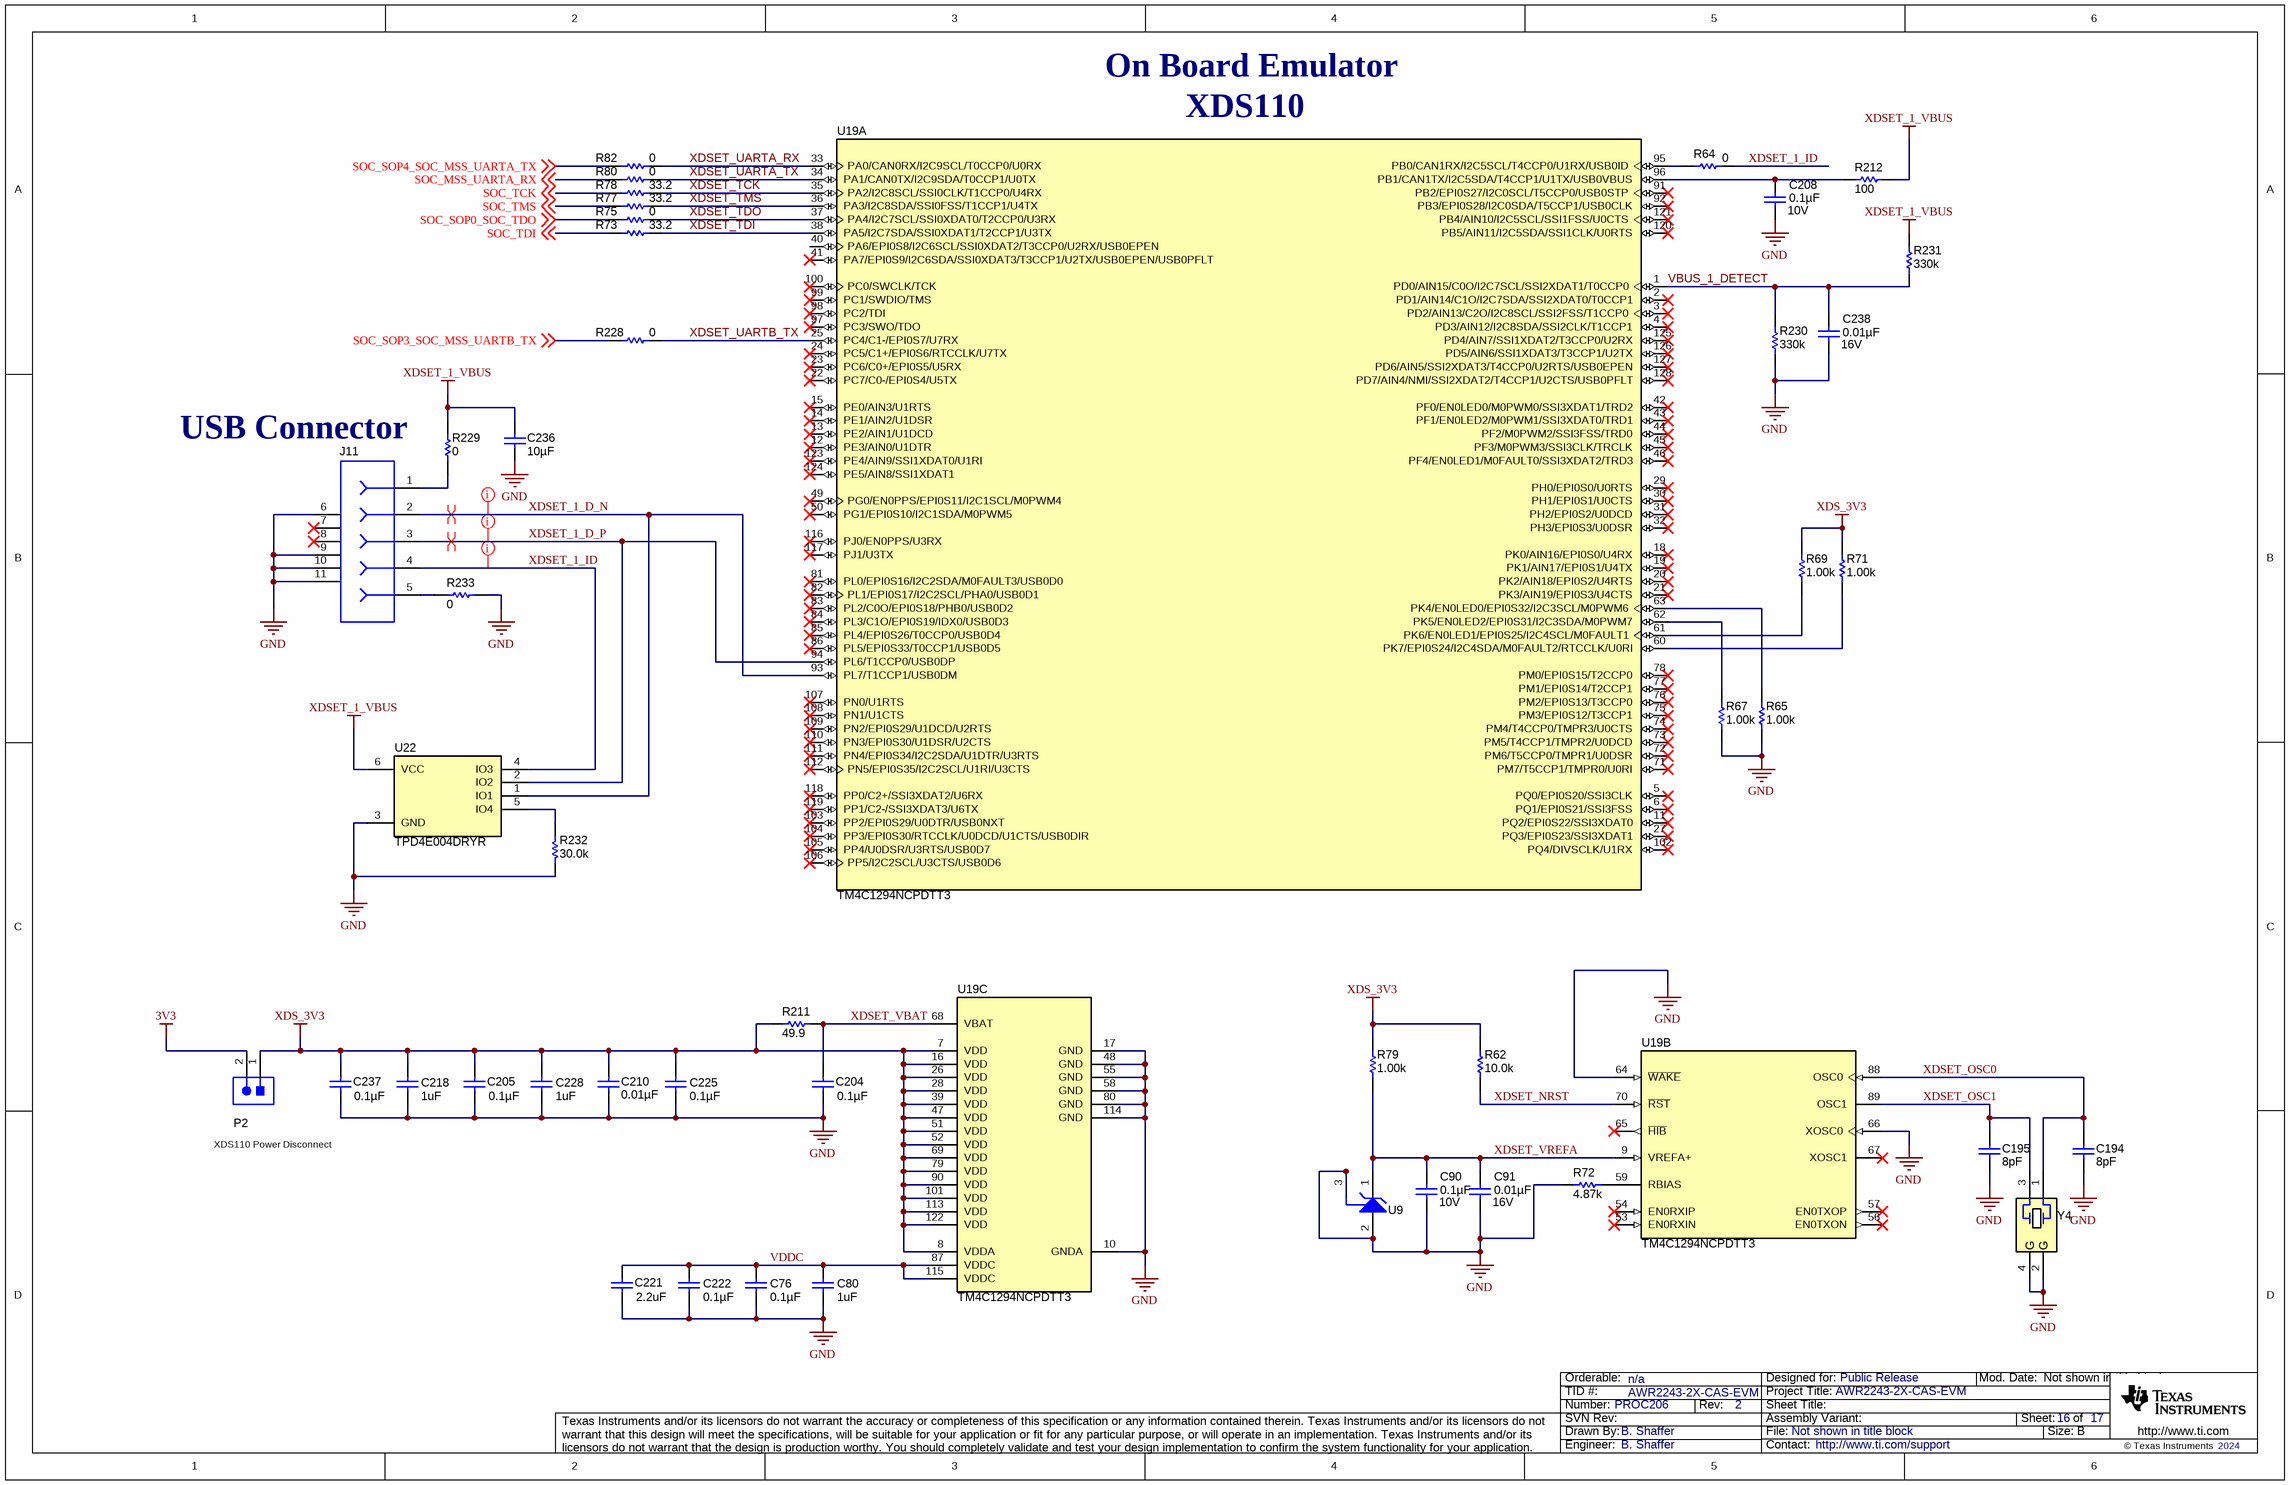
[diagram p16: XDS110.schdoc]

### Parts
C76  ValueDisplayed: 0.1µF  [0402L]  (hidden comment: C0402C104K8RACTU)
C80  ValueDisplayed: 1uF  [0402_070]  (hidden comment: GCM155C71A105KE38D)
C90  VDC_V: 10V  ValueDisplayed: 0.1µF  [0402L]  (hidden comment: C0402C104K8RACTU)
C91  VDC_V: 16V  ValueDisplayed: 0.01µF  [0402L]  (hidden comment: C0402C103K4RACTU)
C194  Cap_F: 8pF  [0402]  (hidden comment: GCM1555C1H8R0DA16D)
C195  Cap_F: 8pF  [0402]  (hidden comment: GCM1555C1H8R0DA16D)
C204  ValueDisplayed: 0.1µF  [0402L]  (hidden comment: C0402C104K8RACTU)
C205  ValueDisplayed: 0.1µF  [0402L]  (hidden comment: C0402C104K8RACTU)
C208  VDC_V: 10V  ValueDisplayed: 0.1µF  [0402L]  (hidden comment: C0402C104K8RACTU)
C210  ValueDisplayed: 0.01µF  [0402S]  (hidden comment: C0402C103K4RACTU)
C218  ValueDisplayed: 1uF  [0402_070]  (hidden comment: GCM155C71A105KE38D)
C221  ValueDisplayed: 2.2uF  [0402_065L]  (hidden comment: C1005X7S1A225K050BC)
C222  ValueDisplayed: 0.1µF  [0402L]  (hidden comment: C0402C104K8RACTU)
C225  ValueDisplayed: 0.1µF  [0402L]  (hidden comment: C0402C104K8RACTU)
C228  ValueDisplayed: 1uF  [0402_070]  (hidden comment: GCM155C71A105KE38D)
C236  Cap_F: 10µF  [0805_HV]  (hidden comment: CL21B106KOQNNNE)
C237  ValueDisplayed: 0.1µF  [0402L]  (hidden comment: C0402C104K8RACTU)
C238  VDC_V: 16V  ValueDisplayed: 0.01µF  [0402L]  (hidden comment: C0402C103K4RACTU)
J11  105017-0001  [CONN_105017-0001]  (value not drawn)
P2  TSW-102-07-G-S  [TSW-102-07-G-S]  (value not drawn)
R62  ValueDisplayed: 10.0k  [0402L]  (hidden comment: CRCW040210K0FKED)
R64  ValueDisplayed: 0  [0402L]  (hidden comment: ERJ-2GE0R00X)
R65  ValueDisplayed: 1.00k  [0402L]  (hidden comment: CRCW04021K00FKED)
R67  ValueDisplayed: 1.00k  [0402L]  (hidden comment: CRCW04021K00FKED)
R69  ValueDisplayed: 1.00k  [0402L]  (hidden comment: CRCW04021K00FKED)
R71  ValueDisplayed: 1.00k  [0402L]  (hidden comment: CRCW04021K00FKED)
R72  ValueDisplayed: 4.87k  [0402L]  (hidden comment: CRCW04024K87FKED)
R73  ValueDisplayed: 33.2  [0402]  (hidden comment: CRCW040233R2FKED)
R75  ValueDisplayed: 0  [0402]  (hidden comment: ERJ-2GE0R00X)
R77  ValueDisplayed: 33.2  [0402]  (hidden comment: CRCW040233R2FKED)
R78  ValueDisplayed: 33.2  [0402]  (hidden comment: CRCW040233R2FKED)
R79  ValueDisplayed: 1.00k  [0402L]  (hidden comment: CRCW04021K00FKED)
R80  ValueDisplayed: 0  [0402]  (hidden comment: ERJ-2GE0R00X)
R82  ValueDisplayed: 0  [0402]  (hidden comment: ERJ-2GE0R00X)
R211  ValueDisplayed: 49.9  [0402L]  (hidden comment: CRCW040249R9FKED)
R212  ValueDisplayed: 100  [0402L]  (hidden comment: ERJ-2GEJ101X)
R228  ValueDisplayed: 0  [0402]  (hidden comment: ERJ-2GE0R00X)
R229  ValueDisplayed: 0  [0603]  (hidden comment: MCT06030Z0000ZP500)
R230  ValueDisplayed: 330k  [0402L]  (hidden comment: CRCW0402330KFKED)
R231  ValueDisplayed: 330k  [0402L]  (hidden comment: CRCW0402330KFKED)
R232  ValueDisplayed: 30.0k  [0402L]  (hidden comment: CRCW040230K0FKED)
R233  ValueDisplayed: 0  [0603]  (hidden comment: MCT06030Z0000ZP500)
U9  LM4040C25QDBZR  [DBZ0003A_N]  (value not drawn)
U19  TM4C1294NCPDTT3  [PDT0128A]  (parts A,B,C of 3)
U22  TPD4E004DRYR  [DRY0006A]
Y4  NX3225SA-16.000M-STD-CRS-2  [NDK_NX3225SA]  (value not drawn)

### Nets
3V3: P2.2
GND: C76.1 C80.2 C90.1 C91.1 C194.2 C195.1 C204.2 C205.1 C208.1 C210.2 C218.2 C221.1 C222.1 C225.1 C228.2 C236.2 C237.1 C238.1 J11.6 J11.9 J11.10 J11.11 R65.1 R67.1 R72.1 R230.1 R232.1 R233.1 U9.2(ANODE) U9.3(NC) U19.10(GNDA) U19.17(GND) U19.48(GND) U19.55(GND) U19.58(GND) U19.64(~{WAKE}) U19.66(XOSC0) U19.80(GND) U19.114(GND) U22.3(GND) Y4.2(GND) Y4.4(GND)
XDS_3V3: C205.2 C210.1 C218.1 C225.2 C228.1 C237.2 P2.1 R62.2 R69.2 R71.2 R79.2 R211.2 U19.7(VDD) U19.8(VDDA) U19.16(VDD) U19.26(VDD) U19.28(VDD) U19.39(VDD) U19.47(VDD) U19.51(VDD) U19.52(VDD) U19.69(VDD) U19.79(VDD) U19.90(VDD) U19.101(VDD) U19.113(VDD) U19.122(VDD)
XDSET_1_VBUS: C236.1 R212.2 R229.2 R231.2 U22.6(VCC)
SOC_MSS_UARTA_RX: R80.1 ; off-sheet SOC_MSS_UARTA_RX
SOC_SOP0_SOC_TDO: R75.1 ; off-sheet SOC_SOP0_SOC_TDO
SOC_SOP3_SOC_MSS_UARTB_TX: R228.1 ; off-sheet SOC_SOP3_SOC_MSS_UARTB_TX
SOC_SOP4_SOC_MSS_UARTA_TX: R82.1 ; off-sheet SOC_SOP4_SOC_MSS_UARTA_TX
SOC_TCK: R78.1 ; off-sheet SOC_TCK
SOC_TDI: R73.1 ; off-sheet SOC_TDI
SOC_TMS: R77.1 ; off-sheet SOC_TMS
VBUS_1_DETECT: C238.2 R230.2 R231.1 U19.1(PD0/AIN15/C0O/I2C7SCL/SSI2XDAT1/T0CCP0)
VDDC: C76.2 C80.1 C221.2 C222.2 U19.87(VDDC) U19.115(VDDC)
XDSET_1_D_N: J11.2 U19.93(PL7/T1CCP1/USB0DM) U22.1(IO1)
XDSET_1_D_P: J11.3 U19.94(PL6/T1CCP0/USB0DP) U22.2(IO2)
XDSET_1_ID: J11.4 R64.1 U22.4(IO3)
XDSET_NRST: R62.1 U19.70(~{RST})
XDSET_OSC0: C194.1 U19.88(OSC0) Y4.1
XDSET_OSC1: C195.2 U19.89(OSC1) Y4.3
XDSET_TCK: R78.2 U19.35(PA2/I2C8SCL/SSI0CLK/T1CCP0/U4RX)
XDSET_TDI: R73.2 U19.38(PA5/I2C7SDA/SSI0XDAT1/T2CCP1/U3TX)
XDSET_TDO: R75.2 U19.37(PA4/I2C7SCL/SSI0XDAT0/T2CCP0/U3RX)
XDSET_TMS: R77.2 U19.36(PA3/I2C8SDA/SSI0FSS/T1CCP1/U4TX)
XDSET_UARTA_RX: R82.2 U19.33(PA0/CAN0RX/I2C9SCL/T0CCP0/U0RX)
XDSET_UARTA_TX: R80.2 U19.34(PA1/CAN0TX/I2C9SDA/T0CCP1/U0TX)
XDSET_UARTB_TX: R228.2 U19.25(PC4/C1-/EPI0S7/U7RX)
XDSET_VBAT: C204.1 R211.1 U19.68(VBAT)
XDSET_VREFA: C90.2 C91.2 R79.1 U9.1(CATHODE) U19.9(VREFA+)
NetC208_2: C208.2 R212.1 U19.96(PB1/CAN1TX/I2C5SDA/T4CCP1/U1TX/USB0VBUS)
NetJ11_1: J11.1 R229.1
NetJ11_5: J11.5 R233.2
NetR64_2: R64.2 U19.95(PB0/CAN1RX/I2C5SCL/T4CCP0/U1RX/USB0ID)
NetR65_2: R65.2 U19.63(PK4/EN0LED0/EPI0S32/I2C3SCL/M0PWM6)
NetR67_2: R67.2 U19.62(PK5/EN0LED2/EPI0S31/I2C3SDA/M0PWM7)
NetR69_1: R69.1 U19.61(PK6/EN0LED1/EPI0S25/I2C4SCL/M0FAULT1)
NetR71_1: R71.1 U19.60(PK7/EPI0S24/I2C4SDA/M0FAULT2/RTCCLK/U0RI)
NetR72_2: R72.2 U19.59(RBIAS)
NetR232_2: R232.2 U22.5(IO4)

Not connected (* = marked no-connect by the designer): J11 7* 8*; U19 2(PD1/AIN14/C1O/I2C7SDA/SSI2XDAT0/T0CCP1)* 3(PD2/AIN13/C2O/I2C8SCL/SSI2FSS/T1CCP0)* 4(PD3/AIN12/I2C8SDA/SSI2CLK/T1CCP1)* 5(PQ0/EPI0S20/SSI3CLK)* 6(PQ1/EPI0S21/SSI3FSS)* 11(PQ2/EPI0S22/SSI3XDAT0)* 12(PE3/AIN0/U1DTR)* 13(PE2/AIN1/U1DCD)* 14(PE1/AIN2/U1DSR)* 15(PE0/AIN3/U1RTS)* 18(PK0/AIN16/EPI0S0/U4RX)* 19(PK1/AIN17/EPI0S1/U4TX)* 20(PK2/AIN18/EPI0S2/U4RTS)* 21(PK3/AIN19/EPI0S3/U4CTS)* 22(PC7/C0-/EPI0S4/U5TX)* 23(PC6/C0+/EPI0S5/U5RX)* 24(PC5/C1+/EPI0S6/RTCCLK/U7TX)* 27(PQ3/EPI0S23/SSI3XDAT1)* 29(PH0/EPI0S0/U0RTS)* 30(PH1/EPI0S1/U0CTS)* 31(PH2/EPI0S2/U0DCD)* 32(PH3/EPI0S3/U0DSR)* 40(PA6/EPI0S8/I2C6SCL/SSI0XDAT2/T3CCP0/U2RX/USB0EPEN) 41(PA7/EPI0S9/I2C6SDA/SSI0XDAT3/T3CCP1/U2TX/USB0EPEN/USB0PFLT)* 42(PF0/EN0LED0/M0PWM0/SSI3XDAT1/TRD2)* 43(PF1/EN0LED2/M0PWM1/SSI3XDAT0/TRD1)* 44(PF2/M0PWM2/SSI3FSS/TRD0)* 45(PF3/M0PWM3/SSI3CLK/TRCLK)* 46(PF4/EN0LED1/M0FAULT0/SSI3XDAT2/TRD3)* 49(PG0/EN0PPS/EPI0S11/I2C1SCL/M0PWM4)* 50(PG1/EPI0S10/I2C1SDA/M0PWM5)* 53(EN0RXIN)* 54(EN0RXIP)* 56(EN0TXON)* 57(EN0TXOP)* 65(~{HIB})* 67(XOSC1)* 71(PM7/T5CCP1/TMPR0/U0RI)* 72(PM6/T5CCP0/TMPR1/U0DSR)* 73(PM5/T4CCP1/TMPR2/U0DCD)* 74(PM4/T4CCP0/TMPR3/U0CTS)* 75(PM3/EPI0S12/T3CCP1)* 76(PM2/EPI0S13/T3CCP0)* 77(PM1/EPI0S14/T2CCP1)* 78(PM0/EPI0S15/T2CCP0)* 81(PL0/EPI0S16/I2C2SDA/M0FAULT3/USB0D0)* 82(PL1/EPI0S17/I2C2SCL/PHA0/USB0D1)* 83(PL2/C0O/EPI0S18/PHB0/USB0D2)* 84(PL3/C1O/EPI0S19/IDX0/USB0D3)* 85(PL4/EPI0S26/T0CCP0/USB0D4)* 86(PL5/EPI0S33/T0CCP1/USB0D5)* 91(PB2/EPI0S27/I2C0SCL/T5CCP0/USB0STP)* 92(PB3/EPI0S28/I2C0SDA/T5CCP1/USB0CLK)* 97(PC3/SWO/TDO)* 98(PC2/TDI)* 99(PC1/SWDIO/TMS)* 100(PC0/SWCLK/TCK)* 102(PQ4/DIVSCLK/U1RX)* 103(PP2/EPI0S29/U0DTR/USB0NXT)* 104(PP3/EPI0S30/RTCCLK/U0DCD/U1CTS/USB0DIR)* 105(PP4/U0DSR/U3RTS/USB0D7)* 106(PP5/I2C2SCL/U3CTS/USB0D6)* 107(PN0/U1RTS)* 108(PN1/U1CTS)* 109(PN2/EPI0S29/U1DCD/U2RTS)* 110(PN3/EPI0S30/U1DSR/U2CTS)* 111(PN4/EPI0S34/I2C2SDA/U1DTR/U3RTS)* 112(PN5/EPI0S35/I2C2SCL/U1RI/U3CTS)* 116(PJ0/EN0PPS/U3RX)* 117(PJ1/U3TX)* 118(PP0/C2+/SSI3XDAT2/U6RX)* 119(PP1/C2-/SSI3XDAT3/U6TX)* 120(PB5/AIN11/I2C5SDA/SSI1CLK/U0RTS)* 121(PB4/AIN10/I2C5SCL/SSI1FSS/U0CTS)* 123(PE4/AIN9/SSI1XDAT0/U1RI)* 124(PE5/AIN8/SSI1XDAT1)* 125(PD4/AIN7/SSI1XDAT2/T3CCP0/U2RX)* 126(PD5/AIN6/SSI1XDAT3/T3CCP1/U2TX)* 127(PD6/AIN5/SSI2XDAT3/T4CCP0/U2RTS/USB0EPEN)* 128(PD7/AIN4/NMI/SSI2XDAT2/T4CCP1/U2CTS/USB0PFLT)*

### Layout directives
differential pair: XDSET_1_D_N, XDSET_1_D_P
net class XDS_USB: XDSET_1_D_N, XDSET_1_D_P, XDSET_1_ID

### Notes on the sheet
- On Board Emulator
- (near U19) XDS110
- USB Connector
- XDS110 Power Disconnect

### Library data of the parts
C76 C205 C222 C225 C237 = CMP-0078241-1: CAP, CERM, 0.1 µF, 10 V,+/- 10%, X7R, 0402; Manufacturer: Kemet; TaMin_C: -55°C; Polarized: N; SizeAreaWB_mm2: 3; U/M: EA; Value: 0.1uF; TaMax_C: 125°C; SizeZ_mm: 0.6; SizeX_mm: 1; SizeY_mm: 0.5; Cap_Case: 0402; Value2: 10V; Cap_F: 100nF; AEC Category: Q200
C80 C218 C228 = CMP-0006349-2: CAP, CERM, 1 uF, 10 V, +/- 10%, X7S, AEC-Q200 Grade 1, 0402; Manufacturer: MuRata; TaMin_C: -55°C; Polarized: N; SizeAreaWB_mm2: 3; Value1: Unknown; U/M: EA; Value: 1uF; TaMax_C: 125°C; SizeZ_mm: 0.7; SizeX_mm: 1; SizeY_mm: 0.5; Cap_Case: 0402; Value2: 10V; AEC Qualified: Y; Cap_F: 1µF; AEC Category: Q200
C90 C208 = CMP-0078241-1: as C82 on sheet Temp
C91 C238 = CMP-0078218-1: CAP, CERM, 0.01 µF, 16 V,+/- 10%, X7R, 0402; Manufacturer: Kemet; TaMin_C: -55°C; Polarized: N; Green_Lifecycle: Active; SizeAreaWB_mm2: 3; Green_REACh: Passed; U/M: EA; Value: 0.01uF; TaMax_C: 125°C; SizeZ_mm: 0.6; SizeX_mm: 1; SizeY_mm: 0.5; Cap_Case: 0402; CompType: Capacitor; Cap_F: 10nF; AEC Category: Q200
C194 C195 = CMP-0087060-3: Cap Ceramic 8pF 50V C0G 0.5pF SMD 0402 125C Paper T/R; Manufacturer: Murata Electronics North America; TempCo: 30ppm/°C; AEC Qualified: Yes; AEC Grade: Grade 1; SizeZ_mm: 0.55mm
C204 = CMP-0078241-1: CAP, CERM, 0.1 µF, 10 V,+/- 10%, X7R, 0402; Manufacturer: Kemet; TaMin_C: -55°C; Polarized: N; SizeAreaWB_mm2: 3; U/M: EA; Value: 0.1uF; TaMax_C: 125°C; SizeZ_mm: 0.6; SizeX_mm: 1; SizeY_mm: 0.5; Cap_Case: 0402; Value2: 10V; CompType: Capacitor; Cap_F: 100nF; AEC Category: Q200
C210 = CMP-0078218-1: CAP, CERM, 0.01 µF, 16 V,+/- 10%, X7R, 0402; Manufacturer: Kemet; TaMin_C: -55°C; Polarized: N; Green_Lifecycle: Active; SizeAreaWB_mm2: 3; Green_REACh: Passed; U/M: EA; Value: 0.01uF; TaMax_C: 125°C; SizeZ_mm: 0.6; SizeX_mm: 1; SizeY_mm: 0.5; Cap_Case: 0402; Value2: 16V; Cap_F: 10nF; AEC Category: Q200
C221 = CMP-0006302-2: CAP, CERM, 2.2 uF, 10 V, +/- 10%, X7S, 0402; Manufacturer: TDK; TaMin_C: -55°C; ESR_ohm: 5.925m; Polarized: N; SizeAreaWB_mm2: 3; Value1: 0.005925 ohm; U/M: EA; Value: 2.2uF; TaMax_C: 125°C; SizeZ_mm: 0.65; SizeX_mm: 1; SizeY_mm: 0.5; Cap_Case: 0402_065; Value2: 10V; CompType: Capacitor; Cap_F: 2.2µF; IRMS_A: 2.05591A; AEC Category: Q200
C236 = CMP-0007995-2: CAP, CERM, 10 uF, 16 V, +/- 10%, X7R, 0805; Manufacturer: Samsung Electro-Mechanics; TaMin_C: -55°C; Polarized: N; SizeAreaWB_mm2: 6.75; Value1: Unknown; U/M: EA; Value: 10uF; TaMax_C: 125°C; SizeZ_mm: 1.45; SizeX_mm: 2; SizeY_mm: 1.25; Cap_Case: 0805; Value2: 16V; SizeArea_mm2: 2.5; AEC Category: Q200
J11 = CMP-0055293-1: Connector, Receptacle, Micro-USB Type B, R/A, Bottom Mount SMT; Manufacturer: Molex; CNHeader: FALSE; Green_Lifecycle: Active; Gender: Female; Green_REACh: Passed; CompType: USB; CT: TRUE
P2 = CMP-0075405-3: Header, 100mil, 2x1, Gold, TH; Manufacturer: Samtec; Pitch_mm: 2.54; Cert_VDE: N; Gender: Male; Cert_CSA: Y; Voltage_V: 550V; Green_REACh: Passed; Current_A: 6.3A; Green_Lifecycle: Active; Row_Count: 1
R62 = CMP-0025958-3: as R10 on sheet Temp
R64 = CMP-0026992-3: RES, 0, 5%, 0.1 W, AEC-Q200 Grade 0, 0402; Manufacturer: Panasonic; Power_W: 100mW; TempCo: 600 ppm/C; Value_Code: 0000; Value: 0; EIA_Code: E24; SizeX_mm: 1; SizeY_mm: 0.5; SizeZ_mm: 0.6; Value2: 0.1W; AEC Qualified: Y; VDC_V: 50V; AEC Category: Q200; SizeAreaWB_mm2: 3
R65 R67 R69 R71 R79 = CMP-0026071-3: as R101 on sheet Enet_Conn
R72 = CMP-0026413-2: RES, 4.87 k, 1%, 0.063 W, AEC-Q200 Grade 0, 0402; Manufacturer: Vishay-Dale; Power_W: 63mW; TempCo: 100 ppm/C; Value_Code: 4k87; Value: 4.87k; EIA_Code: E96; SizeX_mm: 1; SizeY_mm: 0.5; SizeZ_mm: 0.6; Value2: 0.063W; AEC Qualified: Y; VDC_V: 50V; AEC Category: Q200; AEC Grade: 0
R73 R77 R78 = CMP-0026299-2: RES, 33.2, 1%, 0.063 W, AEC-Q200 Grade 0, 0402; Manufacturer: Vishay-Dale; Power_W: 63mW; TempCo: 100 ppm/C; Value_Code: 33R2; Value: 33.2; EIA_Code: E96; SizeX_mm: 1; SizeY_mm: 0.5; SizeZ_mm: 0.6; Value2: 0.063W; AEC Qualified: Y; VDC_V: 50V; AEC Category: Q200; AEC Grade: 0
R75 R80 R82 R228 = CMP-0026992-3: RES, 0, 5%, 0.1 W, AEC-Q200 Grade 0, 0402; Manufacturer: Panasonic; Power_W: 100mW; TempCo: 600 ppm/C; Value_Code: 0000; Value: 0; EIA_Code: E24; SizeX_mm: 1; SizeY_mm: 0.5; SizeZ_mm: 0.6; Value2: 0.1W; CompType: Resistor; AEC Qualified: Y; VDC_V: 50V; AEC Category: Q200; SizeAreaWB_mm2: 3; INSTALLATION: DNP
R211 = CMP-0026404-2: as R198 on sheet Clock_Buff
R212 = CMP-0026993-2: RES, 100, 5%, 0.1 W, AEC-Q200 Grade 0, 0402; Manufacturer: Panasonic; Power_W: 100mW; TempCo: 200 ppm/C; Value_Code: 100R; U/M: EA; Value: 100; EIA_Code: E24; SizeX_mm: 1; SizeY_mm: 0.5; SizeZ_mm: 0.6; Value2: 0.1W; AEC Qualified: Y; AEC Grade: 0; AEC Category: Q200
R229 R233 = CMP-0025884-3: RES, 0, 5%, 0.125 W, 0603; Manufacturer: Vishay/Beyschlag; Power_W: 125mW; TempCo: ppm/C; Value_Code: 0000; U/M: EA; Value: 0; EIA_Code: E24; SizeX_mm: 1.6; SizeY_mm: 0.8; SizeZ_mm: 1; Value2: 0.125W; SizeArea_mm2: 1.28; AEC Qualified: N; AEC Category: Q200
R230 R231 = CMP-0078210-2: RES, 330 k, 1%, 0.063 W, AEC-Q200 Grade 0, 0402; Manufacturer: Vishay-Dale; SizeArea_mm2: 0.5; AEC Qualified: Y; AEC Category: Q200; Value: 330k; SizeZ_mm: 0.6; TempCo: 100 ppm/C; AEC Grade: 0; Power_W: 63mW; VDC_V: 50V; Value2: 0.063W; SizeX_mm: 1
R232 = CMP-0078244-2: RES, 30.0 k, 1%, 0.063 W, AEC-Q200 Grade 0, 0402; Manufacturer: Vishay-Dale; Power_W: 63mW; Green_Lifecycle: Active; TempCo: 100 ppm/C; Value_Code: 30k0; Green_REACh: Passed; Value: 30.0k; Res_ohm: 30k; SizeX_mm: 1; SizeY_mm: 0.5; SizeZ_mm: 0.6; Value2: 0.063W; AEC Qualified: Y; VDC_V: 50V; AEC Grade: 0; AEC Category: Q200
U9 = CMP-0033001-1: Precision Micropower Shunt Voltage Reference, 0.5% accuracy, 2.5 V, 15 ppm / degC, 15 mA, -40 to 125 degC, 3-pin SOT-23 (DBZ), Green (RoHS & no Sb/Br); Manufacturer: Texas Instruments; Initial Accuracy @ 25/deg C(%): 0.5; Temp Coeff(Typ)(ppm/ degree C): 15; Temp Coeff(Max)(ppm/ degree C): 100; Rating: Catalog; Min Iz for Regulation(uA): 75; VO(V): 2.5
U19 = CMP-0029856-2: Tiva C Series Microcontroller, 1024 KB Flash, 256 KB SRAM, 12 Bit, 20 Channels, -40 to 105 degC, 128-Pin TQFP (PDT), Green (RoHS & no Sb/Br), Tray; Manufacturer: Texas Instruments; ADC Channels: 20; CPU: ARM Cortex-M4; Flash: 1024 KB; ADC Resolution: 12 Bits; Max Speed: 120 MHz; SRAM: 256 KB; SizeAreaWB_mm2: 324.0; SizeArea_mm2: 256.0; SizeX_mm: 16.0; SizeZ_mm: 1.2; CompType: IC
U22 = CMP-0043115-3: 4-Channel ESD Protection Array for High-Speed Data Interfaces, DRY0006A (USON-6); Manufacturer: Texas Instruments; IO Leakage Current(nA): 1; USB High Speed: TRUE; IO Capacitance(Typ)(pF): 1.6; Eco-Plan: Green (RoHS & no Sb/Br); IEC 61000-4-2 Contact(+/- kV): 8; Breakdown Voltage(Min)(V): 6; IEC 61000-4-2 Air-Gap(+/- kV): 12; AEC Category: Q200; AEC Qualified: N; CompType: IC; SizeArea_mm2: 1.45; SizeAreaWB_mm2: 4.9; SizeX_mm: 1.0; SizeZ_mm: 0.6; Rating: Catalog
Y4 = CMP-0078214-2: Crystal, 16 MHz, 15 ppm, 8 pF, AEC-Q200 Grade 1, SMD; Manufacturer: NDK; TaMin_C: -40°C; Frequency Tolerance: 10 ppm; Frequency Stability: 150 ppm; Load Capacitance: 7.36 pF; Frequency_Fixed: 16MHz; TaMax_C: 125°C; AEC Qualified: N; AEC Grade: 1; AEC Category: Q200

## Sheet Hardware.SchDoc: Hardware
size 431 x 279 mm; Date: Not shown in title block; ApprovedBy: Not shown in title block; CheckedBy: Not shown in title block; Author: Not shown in title block; CompanyName: Not shown in title block; DrawnBy: B. Shaffer; Engineer: Not shown in title block; Organization: Not shown in title block; Address1: Not shown in title block; Address2: Not shown in title block; Address3: Not shown in title block; Address4: Not shown in title block; DocumentNumber: 17; Revision: Use project parameter SCH_Rev; SheetNumber: 17; SheetTotal: 17; PageSetup: Record=PageOptions¦CenterHorizontal=True¦CenterVertical=True¦PrintScale=1.00¦XCorrection=1.00¦YCorrection=1.00¦PrintKind=0¦BorderSize=5000000¦LeftOffset=0¦BottomOffset=0¦Orientation=2¦PaperLength=1000¦PaperWidth=1000¦Scale=100¦PaperSource=15¦PrintQuality=600¦MediaType=1¦DitherType=10¦PaperKind=Letter¦PrintScaleMode=1
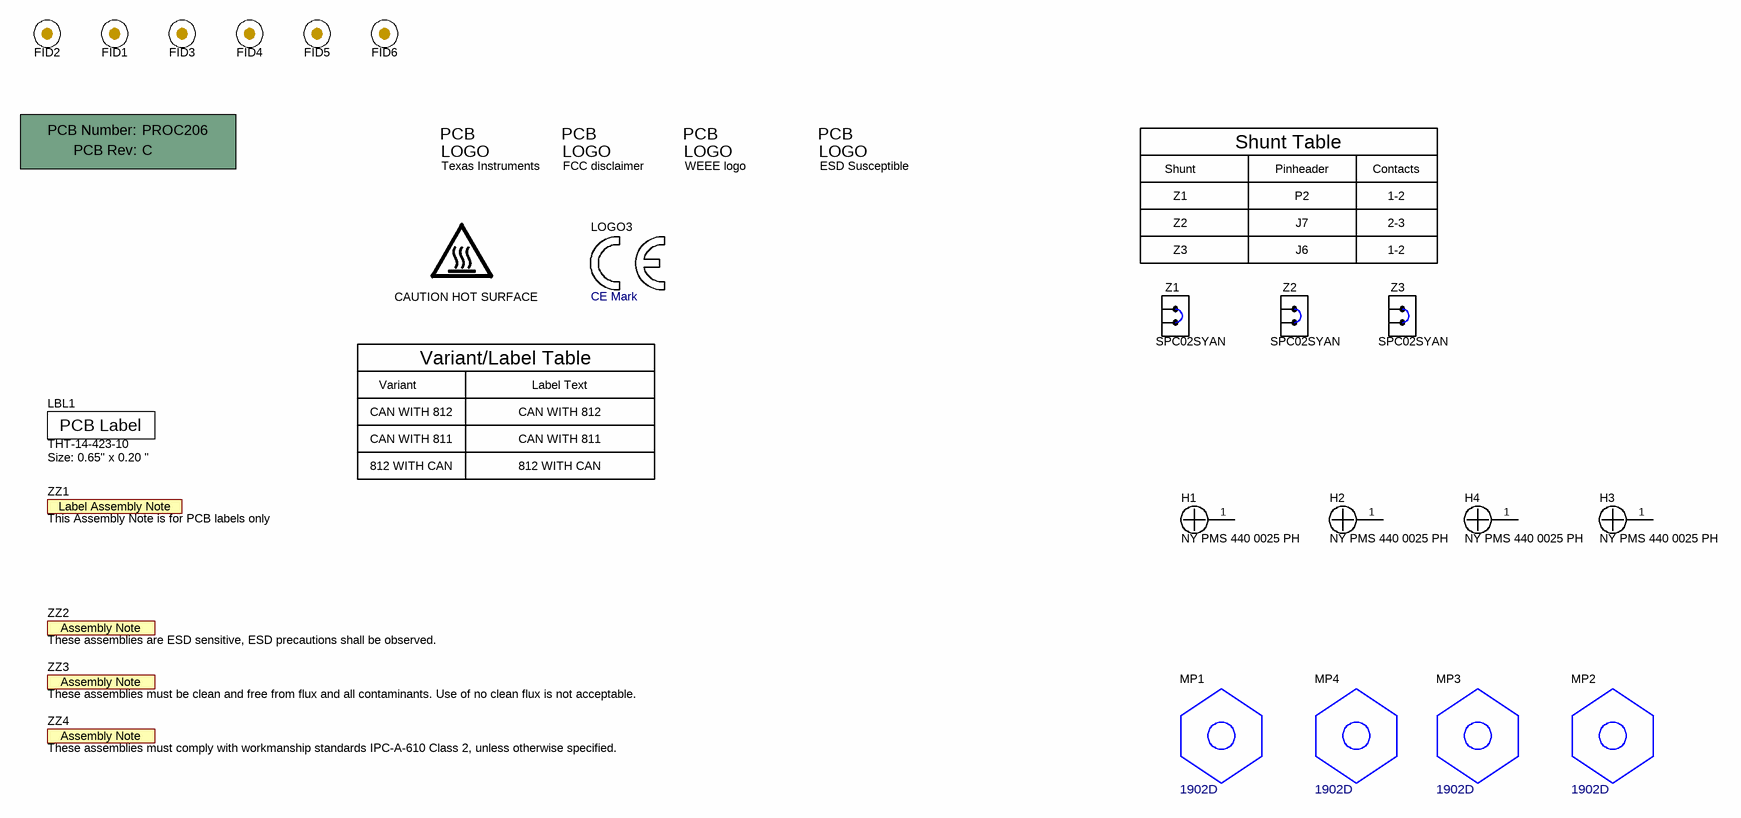
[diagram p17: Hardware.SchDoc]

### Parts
!PCB1  Printed Circuit Board  (value not drawn)  (mechanical)
CAUTION_HOT_SURFACE1  CAUTION HOT SURFACE  [IEC_HotSurface_Small]  (no BOM)
ESD_Susceptible1  ESD Susceptible  [ESD_Overlay_Small]  (no BOM)
FID1  Fiducial  [Fiducial10-20]  (value not drawn)
FID2  Fiducial  [Fiducial10-20]  (value not drawn)
FID3  Fiducial  [Fiducial10-20]  (value not drawn)
FID4  Fiducial  [Fiducial10-20]  (value not drawn)
FID5  Fiducial  [Fiducial10-20]  (value not drawn)
FID6  Fiducial  [Fiducial10-20]  (value not drawn)
H1  NY PMS 440 0025 PH  [NY PMS 440 0025 PH]
H2  NY PMS 440 0025 PH  [NY PMS 440 0025 PH]
H3  NY PMS 440 0025 PH  [NY PMS 440 0025 PH]
H4  NY PMS 440 0025 PH  [NY PMS 440 0025 PH]
LBL1  THT-14-423-10  Note: Size: 0.65" x 0.20 "  [Label_650x200]
Logo1  FCC disclaimer  [FCC_disclaimer]  (no BOM)
Logo2  Texas Instruments  [TI_Stacked_Overlay_Small]  (no BOM)
LOGO3  CE Mark  [CE_Mark_5mm]  (no BOM)
Logo4  WEEE logo  [WEEE_Minimum]  (no BOM)
MP1  1902D  [FP-1902D_HEX_STANDOFF_#4-40-MFG]
MP2  1902D  [FP-1902D_HEX_STANDOFF_#4-40-MFG]
MP3  1902D  [FP-1902D_HEX_STANDOFF_#4-40-MFG]
MP4  1902D  [FP-1902D_HEX_STANDOFF_#4-40-MFG]
Z1  SPC02SYAN  [SPC02SYAN]  (mechanical)
Z2  SPC02SYAN  [SPC02SYAN]  (mechanical)
Z3  SPC02SYAN  [SPC02SYAN]  (mechanical)
ZZ1  This Assembly Note is for PCB labels only  [AssemblyNoteLabel]  (no BOM)
ZZ2  These assemblies are ESD sensitive, ESD precautions shall be observed.  [AssemblyNote]  (no BOM)
ZZ3  These assemblies must be clean and free from flux and all contaminants. Use of no clean flux is not acceptable.  [AssemblyNote]  (no BOM)
ZZ4  These assemblies must comply with workmanship standards IPC-A-610 Class 2, unless otherwise specified.  [AssemblyNote]  (no BOM)

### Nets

Not connected (* = marked no-connect by the designer): H1 1; H2 1; H3 1; H4 1

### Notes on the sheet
- Shunt
- Shunt Table
- Pinheader
- Contacts
- Z1
- Z2
- Z3
- P2
- J7
- J6
- 1-2
- 2-3
- Variant
- Variant/Label Table
- Label Text
- CAN WITH 812
- CAN WITH 811
- 812 WITH CAN

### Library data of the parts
!PCB1 = CMP-0003618-2: Manufacturer: Any; PartNumber: PROC206
CAUTION_HOT_SURFACE1 = CMP-0074837-1: IEC 61010-1 Hot Surface Warning; Library Reference: IEC_HotSurface; SymbolCreator: a0412235
ESD_Susceptible1 = CMP-0074840-1: ESD Susceptible Symbol; Library Reference: Logo; SymbolCreator: a0412235; Lib Reference: ESD_Susceptible
FID1-FID6 = CMP-0077181-1: Fiducial mark.  There is nothing to buy or mount.
H1-H4 = NY PMS 440 0025 PH: Machine Screw, Round, #4-40 x 1/4, Nylon, Philips panhead; Manufacturer: B&F Fastener Supply; CompType: Hardware; SymbolCreator: codlsc; U/M: EA
LBL1 = CMP-0003625-1: Thermal Transfer Printable Labels, 0.650" W x 0.200" H - 10,000 per roll; Manufacturer: Brady; CompType: Label; Value: TPR12EVM
Logo1 = CMP-0074847-1: FCC_disclaimer; Library Reference: Logo
Logo2 = CMP-0074838-1: Texas Instrument Corporate Signature; SymbolCreator: a0412235; Lib Reference: TI_Logo; Library Reference: Logo
LOGO3 = CMP-0074844-1: SymbolCreator: a0412235
Logo4 = CMP-0074769-1
MP1-MP4 = CMP-0089174-1: Manufacturer: Keystone Electronics; SizeZ_mm: 19.43mm; AEC Qualified: No
Z1-Z3 = CMP-0003642-1: Shunt, 100mil, Flash Gold, Black; Manufacturer: Sullins Connector Solutions; Value: 1x2; Note: You can "mate" this to a header by matching the designator.  i.e. use SH-J3 for header J3
ZZ1 = CMP-0003616-3
ZZ2 = CMP-0077236-1
ZZ3 = CMP-0077237-1
ZZ4 = CMP-0077238-1

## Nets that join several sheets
1V0_A: PMIC (5 pins), FE1_PWR (L5.1 L6.1), Connectors (J9.25 J9.28)
1V0_B: PMIC (5 pins), FE2_PWR (L16.1 L17.1), Connectors (J9.31 J9.34)
1V2: PMIC (5 pins), SOC_PWR (42 pins), FE1_PWR (L8.1), Connectors (J9.7 J9.10)
1V2_FILTERED: PMIC (R223.2), FE1_PWR (16 pins), FE2_PWR (12 pins)
1V7: Pre_Reg (P1.1), SOC_PWR (C10.2 U14#1.U9)
1V8: PMIC (5 pins), SOC_PWR (19 pins), FE1_PWR (L7.1), FE2_PWR (L23.1), Connectors (J9.1 J9.4)
3V3: Pre_Reg (23 pins), PMIC (17 pins), SOC_PWR (14 pins), SOC_IO (14 pins), SOC_FLASH_SOP (7 pins), FE1_PWR (C57.1 U5#1.R13), FE1_IO (9 pins), FE2_PWR (C56.1 U6#1.R13), FE2_IO (9 pins), 2CAN (C119.1 C130.1 U13.5 U16.5), Enet_PHY (FB1.1 R236.1 R237.1), Temp (7 pins), Connectors (6 pins), Clock_Buff (C54.1 L1.1), XDS110 (P2.2)
5V: Pre_Reg (5 pins), PMIC (R220.2), 2CAN (C117.1 C129.1 U13.3 U16.3), Connectors (J9.22)
FE1_1V8_FILTERED: SOC_IO (R26.2), FE1_PWR (18 pins)
FE1_VRF1_FILTERED: SOC_IO (C128.1 U14#2.M2), FE1_PWR (11 pins)
FE1_VRF2_FILTERED: SOC_IO (C123.1 U14#2.T2), FE1_PWR (9 pins), FE1_IO (R44.2)
FE2_1V8_FILTERED: SOC_IO (R138.2), FE2_PWR (18 pins)
FE2_VRF1_FILTERED: SOC_IO (C125.1 U14#2.N1), FE2_PWR (11 pins)
FE2_VRF2_FILTERED: SOC_IO (C25.1 U14#2.M1), FE2_PWR (9 pins), FE2_IO (R45.2)
GND: Pre_Reg (51 pins), PMIC (26 pins), SOC_PWR (117 pins), SOC_IO (22 pins), SOC_FLASH_SOP (10 pins), FE1_PWR (105 pins), FE1_IO (17 pins), FE2_PWR (102 pins), FE2_IO (16 pins), 2CAN (19 pins), Enet_PHY (27 pins), Enet_Conn (14 pins), Temp (5 pins), Connectors (26 pins), Clock_Buff (6 pins), XDS110 (42 pins)
VBAT: Pre_Reg (13 pins), 2CAN (C121.1 R169.2 U13.10), Enet_PHY (C16.1 J7.3 U4.1)
25MHZ_XTAL: SOC_IO (U14#2.E19), Enet_PHY (R129.1)
BOOST_ENABLE: Pre_Reg (R167.2 U18.15), PMIC (U21.26), Connectors (J9.24)
CAN_EN: SOC_IO (U14#2.C17), 2CAN (U13.6)
CAN_FAULT: SOC_IO (U14#2.V12), 2CAN (U13.8)
CAN_FD1_RXD: SOC_IO (U14#2.B2), 2CAN (U16.4)
CAN_FD1_TXD: SOC_IO (U14#2.A2), 2CAN (U16.1)
CAN_FD2_RXD: SOC_IO (U14#2.C1), 2CAN (U13.4)
CAN_FD2_TXD: SOC_IO (U14#2.B1), 2CAN (U13.1)
CAN_INH: Pre_Reg (R207.2), 2CAN (U13.7)
CAN_nSTB: PMIC (R221.2), 2CAN (U13.14)
EPWMA0: SOC_IO (U14#2.E3), Enet_PHY (R126.1)
ETH_TRD_N: Enet_PHY (R105.2), Enet_Conn (C101.2 R103.1)
ETH_TRD_P: Enet_PHY (R109.2), Enet_Conn (C105.1 R108.1)
ETHERNET_EN: PMIC (R218.2), Enet_PHY (R17.2 U10.3)
ETHERNET_INH: Pre_Reg (R206.2), SOC_IO (U14#2.G3), Enet_PHY (U10.10)
ETHERNET_nINT: SOC_IO (U14#2.B17), Enet_PHY (U10.2)
FE1_CLKOUT_TO_PMIC: PMIC (U21.10), FE1_IO (R193.2), Connectors (J9.3)
FE1_CSI2_CLK_N: SOC_IO (U14#2.B6), FE1_IO (U5#2.J14)
FE1_CSI2_CLK_P: SOC_IO (U14#2.A6), FE1_IO (U5#2.J15)
FE1_CSI2_TX0_N: SOC_IO (U14#2.A8), FE1_IO (U5#2.G14)
FE1_CSI2_TX0_P: SOC_IO (U14#2.B8), FE1_IO (U5#2.G15)
FE1_CSI2_TX1_N: SOC_IO (U14#2.A7), FE1_IO (U5#2.H14)
FE1_CSI2_TX1_P: SOC_IO (U14#2.B7), FE1_IO (U5#2.H15)
FE1_CSI2_TX2_N: SOC_IO (U14#2.B5), FE1_IO (U5#2.K14)
FE1_CSI2_TX2_P: SOC_IO (U14#2.A5), FE1_IO (U5#2.K15)
FE1_CSI2_TX3_N: SOC_IO (U14#2.B4), FE1_IO (U5#2.L14)
FE1_CSI2_TX3_P: SOC_IO (U14#2.A4), FE1_IO (U5#2.L15)
FE1_FM_CW_CLKOUT_to_FE2_FM_CW_SYNC_IN: FE1_IO (U5#2.D1), FE2_IO (U6#2.D15)
FE1_GPIO0: SOC_IO (U14#2.W16), FE1_IO (U5#2.N4)
FE1_GPIO1: SOC_IO (U14#2.V15), FE1_IO (U5#2.N7)
FE1_GPIO2: SOC_IO (U14#2.W15), FE1_IO (U5#2.N13)
FE1_I2C_SCL: SOC_IO (U14#2.U15), FE1_IO (R158.2)
FE1_I2C_SDA: SOC_IO (U14#2.V16), FE1_IO (R40.2)
FE1_MCU_CLK_OUT: SOC_IO (U14#2.H1), FE1_IO (U5#2.N9)
FE1_nERROR_OUT: SOC_IO (R47.2), FE1_IO (R181.1 U5#2.N8)
FE1_nRESET: SOC_IO (R161.2), FE1_IO (R179.2 TP32.1 U5#2.P12)
FE1_nWARM_RESET: SOC_IO (R162.2), FE1_IO (R175.1 TP26.1 U5#2.N12)
FE1_OSC_CLKOUT: FE1_IO (U5#2.A14), FE2_IO (C61.2)
FE1_SOP1_SYNC_OUT: FE1_IO (R173.1 R174.2 R183.1), Clock_Buff (R203.2)
FE1_SPI_CLK: SOC_IO (R140.1), FE1_IO (U5#2.R9)
FE1_SPI_CS0: SOC_IO (R141.1 U14#2.T19), FE1_IO (R56.1 U5#2.R7)
FE1_SPI_IRQ: SOC_IO (R136.2 U14#2.U18), FE1_IO (R160.2 U5#2.P6)
FE1_SPI_MISO: SOC_IO (U14#2.R17), FE1_IO (U5#2.P5)
FE1_SPI_MOSI: SOC_IO (R145.1), FE1_IO (U5#2.R8)
FE1_SYNC_FROM_SOC: SOC_IO (U14#2.V17), Clock_Buff (R201.2)
FE1_SYNC_IN: FE1_IO (R185.2 U5#2.N10), Clock_Buff (R195.1)
FE2_CSI2_CLK_N: SOC_IO (U14#2.A11), FE2_IO (U6#2.J14)
FE2_CSI2_CLK_P: SOC_IO (U14#2.B11), FE2_IO (U6#2.J15)
FE2_CSI2_TX0_N: SOC_IO (U14#2.A13), FE2_IO (U6#2.G14)
FE2_CSI2_TX0_P: SOC_IO (U14#2.B13), FE2_IO (U6#2.G15)
FE2_CSI2_TX1_N: SOC_IO (U14#2.B12), FE2_IO (U6#2.H14)
FE2_CSI2_TX1_P: SOC_IO (U14#2.A12), FE2_IO (U6#2.H15)
FE2_CSI2_TX2_N: SOC_IO (U14#2.A10), FE2_IO (U6#2.K14)
FE2_CSI2_TX2_P: SOC_IO (U14#2.B10), FE2_IO (U6#2.K15)
FE2_CSI2_TX3_N: SOC_IO (U14#2.A9), FE2_IO (U6#2.L14)
FE2_CSI2_TX3_P: SOC_IO (U14#2.B9), FE2_IO (U6#2.L15)
FE2_GPIO0: SOC_IO (U14#2.V14), FE2_IO (U6#2.N4)
FE2_GPIO1: SOC_IO (U14#2.U13), FE2_IO (U6#2.N7)
FE2_GPIO2: SOC_IO (U14#2.W14), FE2_IO (U6#2.N13)
FE2_I2C_SCL: SOC_IO (U14#2.W12), FE2_IO (R156.2)
FE2_I2C_SDA: SOC_IO (U14#2.T10), FE2_IO (R41.2)
FE2_MCU_CLK_OUT: SOC_IO (U14#2.J2), FE2_IO (U6#2.N9)
FE2_nERROR_OUT: SOC_IO (R168.2), FE2_IO (R164.1 U6#2.N8)
FE2_nRESET: SOC_IO (R187.2), FE2_IO (R190.2 TP33.1 U6#2.P12)
FE2_nWARM_RESET: SOC_IO (R54.2), FE2_IO (R180.1 TP30.1 U6#2.N12)
FE2_SPI_CLK: SOC_IO (R131.1), FE2_IO (U6#2.R9)
FE2_SPI_CS0: SOC_IO (R24.1 U14#2.U17), FE2_IO (R53.1 U6#2.R7)
FE2_SPI_IRQ: SOC_IO (R128.2 U14#2.W18), FE2_IO (R159.2 U6#2.P6)
FE2_SPI_MISO: SOC_IO (U14#2.V18), FE2_IO (U6#2.P5)
FE2_SPI_MOSI: SOC_IO (R139.1), FE2_IO (U6#2.R8)
FE2_SYNC_IN: FE2_IO (R176.2 U6#2.N10), Clock_Buff (R184.1)
FE_SYNC_BUFFER_ENABLE: SOC_IO (U14#2.A18), Clock_Buff (R199.2)
MDIO_CLK: SOC_IO (U14#2.R19), Enet_PHY (R112.1)
MDIO_DATA: SOC_IO (R15.1 U14#2.P19), Enet_PHY (R16.1)
PMIC_ENABLE: PMIC (R83.1 U21.8), Connectors (J9.9)
PMIC_GPIO1: PMIC (R218.1 R221.1 U21.1), Connectors (J9.27)
PMIC_nINT_OUT: PMIC (R224.1 U21.9), SOC_IO (U14#2.B19), Connectors (J9.6)
PRE_REG_EN: Pre_Reg (R205.2), Connectors (J9.36)
PRE_REG_PG: Pre_Reg (R215.1 U20.10), PMIC (R83.2)
RGMII_RCLK: SOC_IO (U14#2.M19), Enet_PHY (R89.1)
RGMII_RCTL: SOC_IO (U14#2.J17), Enet_PHY (R98.1)
RGMII_RD0: SOC_IO (U14#2.P18), Enet_PHY (R90.1)
RGMII_RD1: SOC_IO (U14#2.N19), Enet_PHY (R91.1)
RGMII_RD2: SOC_IO (U14#2.M18), Enet_PHY (R92.1)
RGMII_RD3: SOC_IO (U14#2.L19), Enet_PHY (R93.1)
RGMII_TCLK: SOC_IO (U14#2.K19), Enet_PHY (R94.1)
RGMII_TCTL: SOC_IO (U14#2.J18), Enet_PHY (R95.1)
RGMII_TD0: SOC_IO (U14#2.L18), Enet_PHY (R104.1)
RGMII_TD1: SOC_IO (U14#2.L17), Enet_PHY (R102.1)
RGMII_TD2: SOC_IO (U14#2.K16), Enet_PHY (R99.1)
RGMII_TD3: SOC_IO (U14#2.K18), Enet_PHY (R97.1)
SOC_I2C_SCL: SOC_IO (R76.1 U14#2.F18), Temp (U2.1 U8.1), Connectors (J9.16)
SOC_I2C_SDA: SOC_IO (R81.1 U14#2.F16), Temp (U2.6 U8.6), Connectors (J9.13)
SOC_LVDS_CLK_N: SOC_IO (U14#2.W7), Connectors (J2.46)
SOC_LVDS_CLK_P: SOC_IO (U14#2.V7), Connectors (J2.44)
SOC_LVDS_FRCLK_N: SOC_IO (U14#2.W8), Connectors (J2.28)
SOC_LVDS_FRCLK_P: SOC_IO (U14#2.V8), Connectors (J2.26)
SOC_LVDS_TX0_N: SOC_IO (U14#2.V6), Connectors (J2.58)
SOC_LVDS_TX0_P: SOC_IO (U14#2.W6), Connectors (J2.56)
SOC_LVDS_TX1_N: SOC_IO (U14#2.V5), Connectors (J2.52)
SOC_LVDS_TX1_P: SOC_IO (U14#2.W5), Connectors (J2.50)
SOC_LVDS_TX2_N: SOC_IO (U14#2.V4), Connectors (J2.40)
SOC_LVDS_TX2_P: SOC_IO (U14#2.W4), Connectors (J2.38)
SOC_LVDS_TX3_N: SOC_IO (U14#2.V3), Connectors (J2.34)
SOC_LVDS_TX3_P: SOC_IO (U14#2.W3), Connectors (J2.32)
SOC_MSS_UARTA_RX: SOC_IO (U14#2.U3), Connectors (J8.2), XDS110 (R80.1)
SOC_nERROR_OUT: PMIC (U21.16), SOC_IO (R32.2 R225.1), Connectors (J9.15)
SOC_nRESET_FROM_EMU: SOC_IO (R142.1), Connectors (R125.2)
SOC_nRESET_FROM_PMIC: PMIC (U21.32), SOC_IO (R143.1), Connectors (J9.33)
SOC_QSPI_CS: SOC_IO (U14#2.F2), SOC_FLASH_SOP (R234.2 R235.2)
SOC_QSPI_D0: SOC_IO (U14#2.C2), SOC_FLASH_SOP (R134.2)
SOC_QSPI_D1: SOC_IO (U14#2.D2), SOC_FLASH_SOP (R148.1 R151.1)
SOC_QSPI_D2: SOC_IO (U14#2.D1), SOC_FLASH_SOP (R149.1 R152.1)
SOC_QSPI_D3: SOC_IO (U14#2.E2), SOC_FLASH_SOP (R130.1 R132.2)
SOC_QSPI_SCLK: SOC_IO (U14#2.E1), SOC_FLASH_SOP (R133.2)
SOC_SOP0_SOC_TDO: SOC_IO (R37.1), SOC_FLASH_SOP (R46.2 R48.1), Connectors (R118.2), XDS110 (R75.1)
SOC_SOP1: SOC_IO (U14#2.E17), SOC_FLASH_SOP (R49.1 R50.2)
SOC_SOP2: SOC_IO (U14#2.F1), SOC_FLASH_SOP (R146.2)
SOC_SOP3_SOC_MSS_UARTB_TX: SOC_IO (U14#2.V9), SOC_FLASH_SOP (R19.2 R21.1), XDS110 (R228.1)
SOC_SOP4_SOC_MSS_UARTA_TX: SOC_IO (U14#2.W2), SOC_FLASH_SOP (R20.1 R22.2), Connectors (J8.3), XDS110 (R82.1)
SOC_SPIB_CS0: PMIC (U21.2), SOC_IO (R36.1 U14#2.D19), Connectors (R219.2)
SOC_SPIB_CS1: SOC_IO (R35.1 U14#2.E18), Connectors (R216.2)
SOC_SPIB_MISO: PMIC (U21.3), SOC_IO (U14#2.C19), Connectors (J9.21)
SOC_SPIB_MOSI: PMIC (U21.5), SOC_IO (R154.1), Connectors (J9.12)
SOC_SPIB_SCLK: PMIC (U21.4), SOC_IO (R153.1), Connectors (J9.18)
SOC_TCK: SOC_IO (U14#2.C3), Connectors (R120.2), XDS110 (R78.1)
SOC_TDI: SOC_IO (U14#2.C5), Connectors (R113.2), XDS110 (R73.1)
SOC_TMS: SOC_IO (U14#2.D4), Connectors (R110.2), XDS110 (R77.1)
VPP_EN: Pre_Reg (R55.2), SOC_IO (U14#2.B18)

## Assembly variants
CAN with 812: not fitted C100 C101 C105 C108 C144 FID1 FID2 FID3 FID4 FID5 FID6 R3 R5 R6 R7 R8 R9 R17 R20 R21 R46 R49 R87 R88 R100 R106 R126 R129 R171 R173 R174 R178 R189 R192 R196 R198 R201 R205 R206 R207 R216 R221 R235 R238 R239
CAN with 811: not fitted C16 C17 C104 C106 C112 C144 C182 D5 FID1 FID2 FID3 FID4 FID5 FID6 J7 R3 R5 R6 R7 R8 R9 R20 R21 R46 R84 R126 R129 R144 R171 R173 R174 R178 R189 R192 R194 R196 R198 R201 R205 R206 R207 R216 R219 R221 R235 R236 S3 U4
812 with CAN: not fitted C100 C101 C105 C108 C144 FID1 FID2 FID3 FID4 FID5 FID6 R3 R5 R6 R7 R8 R9 R20 R21 R46 R49 R87 R88 R100 R106 R126 R129 R171 R173 R174 R178 R189 R192 R196 R198 R201 R205 R206 R207 R216 R221 R235 R238 R239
